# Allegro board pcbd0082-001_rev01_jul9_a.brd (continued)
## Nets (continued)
DDR0_32A_A5: R211.1(N1) U1.T9(DDR0_32A_A5) U17.P2(A5) U18.P2(A5) U19.P2(A5) V1_A-A05.1(PIN) V2_A-A05.1(PIN) V3_A-A05.1(PIN)
DDR0_32A_A6: R212.1(N1) U1.AD7(DDR0_32A_A6) U17.R8(A6) U18.R8(A6) U19.R8(A6) V1_A-A06.1(PIN) V2_A-A06.1(PIN) V3_A-A06.1(PIN)
DDR0_32A_A7: R213.1(N1) U1.R9(DDR0_32A_A7) U17.R2(A7) U18.R2(A7) U19.R2(A7) V1_A-A07.1(PIN) V2_A-A07.1(PIN) V3_A-A07.1(PIN)
DDR0_32A_A8: R214.1(N1) U1.AE7(DDR0_32A_A8) U17.T8(A8) U18.T8(A8) U19.T8(A8) V1_A-A08.1(PIN) V2_A-A08.1(PIN) V3_A-A08.1(PIN)
DDR0_32A_A9: R215.1(N1) U1.AE6(DDR0_32A_A9) U17.R3(A9) U18.R3(A9) U19.R3(A9) V1_A-A09.1(PIN) V2_A-A09.1(PIN) V3_A-A09.1(PIN)
DDR0_32A_A10: R216.1(N1) U1.Y7(DDR0_32A_A10) U17.L7(A10/AP) U18.L7(A10/AP) U19.L7(A10/AP) V1_A-A10.1(PIN) V2_A-A10.1(PIN) V3_A-A10.1(PIN)
DDR0_32A_A11: R217.1(N1) U1.R8(DDR0_32A_A11) U17.R7(A11) U18.R7(A11) U19.R7(A11) V1_A-A11.1(PIN) V2_A-A11.1(PIN) V3_A-A11.1(PIN)
DDR0_32A_A12: R218.1(N1) U1.Y8(DDR0_32A_A12) U17.N7(A12/BC_L) U18.N7(A12/BC_L) U19.N7(A12/BC_L) V1_A-A12.1(PIN) V2_A-A12.1(PIN) V3_A-A12.1(PIN)
DDR0_32A_A13: R219.1(N1) U1.AE8(DDR0_32A_A13) U17.T3(A13) U18.T3(A13) U19.T3(A13) V1_A-A13.1(PIN) V2_A-A13.1(PIN) V3_A-A13.1(PIN)
DDR0_32A_A14: R220.1(N1) U1.R7(DDR0_32A_A14) U17.T7(A14) U18.T7(A14) U19.T7(A14) V1_A-A14.1(PIN) V2_A-A14.1(PIN) V3_A-A14.1(PIN)
DDR0_32A_BA0: R224.1(N1) U1.U9(DDR0_32A_BA0) U17.M2(BA0) U18.M2(BA0) U19.M2(BA0) V1_A-BA0.1(PIN) V2_A-BA0.1(PIN) V3_A-BA0.1(PIN)
DDR0_32A_BA1: R223.1(N1) U1.AB6(DDR0_32A_BA1) U17.N8(BA1) U18.N8(BA1) U19.N8(BA1) V1_A-BA1.1(PIN) V2_A-BA1.1(PIN) V3_A-BA1.1(PIN)
DDR0_32A_BA2: R222.1(N1) U1.AD6(DDR0_32A_BA2) U17.M3(BA2) U18.M3(BA2) U19.M3(BA2) V1_A-BA2.1(PIN) V2_A-BA2.1(PIN) V3_A-BA2.1(PIN)
DDR0_32A_CAS_L: R226.1(N1) U1.AB9(DDR0_32A_CAS_L) U17.K3(CAS_L) U18.K3(CAS_L) U19.K3(CAS_L) V1_A-CAS.1(PIN) V2_A-CAS.1(PIN) V3_A-CAS.1(PIN)
DDR0_32A_CB0: U1.U2(DDR0_32A_CB0) U19.F2(DQ2) V_A-CB0.1(PIN)
DDR0_32A_CB1: U1.T4(DDR0_32A_CB1) U19.H7(DQ7) V_A-CB1.1(PIN)
DDR0_32A_CB2: U1.U4(DDR0_32A_CB2) U19.E3(DQ0) V_A-CB2.1(PIN)
DDR0_32A_CB3: U1.T5(DDR0_32A_CB3) U19.H8(DQ5) V_A-CB3.1(PIN)
DDR0_32A_CB4: U1.T6(DDR0_32A_CB4) U19.F8(DQ3) V_A-CB4.1(PIN)
DDR0_32A_CB5: U1.R5(DDR0_32A_CB5) U19.F7(DQ1) V_A-CB5.1(PIN)
DDR0_32A_CB6: U1.U1(DDR0_32A_CB6) U19.G2(DQ6) V_A-CB6.1(PIN)
DDR0_32A_CB7: U1.T3(DDR0_32A_CB7) U19.H3(DQ4) V_A-CB7.1(PIN)
DDR0_32A_CK0_N: C71.2(N2) R8.1(N1) U1.V7(DDR0_32A_CK_L0) U17.K7(CK_L) U18.K7(CK_L) U19.K7(CK_L)
DDR0_32A_CK0_P: C71.1(N1) R7.1(N1) U1.V8(DDR0_32A_CK_H0) U17.J7(CK) U18.J7(CK) U19.J7(CK)
DDR0_32A_CKE0: R231.1(N1) U1.AC7(DDR0_32A_CKE0) U17.K9(CKE0) U18.K9(CKE0) U19.K9(CKE0)
DDR0_32A_CS0_L: R229.1(N1) U1.W9(DDR0_32A_CS_L0) U17.L2(CS0_L) U18.L2(CS0_L) U19.L2(CS0_L)
DDR0_32A_DM0: U1.AH1(DDR0_32A_DM0) U17.E7(LDM) V_A-DM0.1(PIN)
DDR0_32A_DM1: U1.AD3(DDR0_32A_DM1) U17.D3(UDM) V_A-DM1.1(PIN)
DDR0_32A_DM2: U1.Y5(DDR0_32A_DM2) U18.E7(LDM) V_A-DM2.1(PIN)
DDR0_32A_DM3: U1.V5(DDR0_32A_DM3) U18.D3(UDM) V_A-DM3.1(PIN)
DDR0_32A_DM4: U1.R6(DDR0_32A_DM4) U19.E7(LDM) V_A-DM4.1(PIN)
DDR0_32A_DQ0: U1.AE5(DDR0_32A_DQ0) U17.F2(DQ2) V_A-DQ00.1(PIN)
DDR0_32A_DQ1: U1.AE3(DDR0_32A_DQ1) U17.G2(DQ6) V_A-DQ01.1(PIN)
DDR0_32A_DQ2: U1.AE2(DDR0_32A_DQ2) U17.H8(DQ5) V_A-DQ02.1(PIN)
DDR0_32A_DQ3: U1.AD1(DDR0_32A_DQ3) U17.H7(DQ7) V_A-DQ03.1(PIN)
DDR0_32A_DQ4: U1.AF2(DDR0_32A_DQ4) U17.H3(DQ4) V_A-DQ04.1(PIN)
DDR0_32A_DQ5: U1.AE4(DDR0_32A_DQ5) U17.E3(DQ0) V_A-DQ05.1(PIN)
DDR0_32A_DQ6: U1.AG2(DDR0_32A_DQ6) U17.F7(DQ1) V_A-DQ06.1(PIN)
DDR0_32A_DQ7: U1.AG1(DDR0_32A_DQ7) U17.F8(DQ3) V_A-DQ07.1(PIN)
DDR0_32A_DQ8: U1.AB3(DDR0_32A_DQ8) U17.D7(DQ8) V_A-DQ08.1(PIN)
DDR0_32A_DQ9: U1.AD2(DDR0_32A_DQ9) U17.C3(DQ9) V_A-DQ09.1(PIN)
DDR0_32A_DQ10: U1.AB4(DDR0_32A_DQ10) U17.C8(DQ10) V_A-DQ10.1(PIN)
DDR0_32A_DQ11: U1.AC1(DDR0_32A_DQ11) U17.B8(DQ14) V_A-DQ11.1(PIN)
DDR0_32A_DQ12: U1.AC5(DDR0_32A_DQ12) U17.A2(DQ13) V_A-DQ12.1(PIN)
DDR0_32A_DQ13: U1.AC2(DDR0_32A_DQ13) U17.A7(DQ12) V_A-DQ13.1(PIN)
DDR0_32A_DQ14: U1.AD4(DDR0_32A_DQ14) U17.A3(DQ15) V_A-DQ14.1(PIN)
DDR0_32A_DQ15: U1.AD5(DDR0_32A_DQ15) U17.C2(DQ11) V_A-DQ15.1(PIN)
DDR0_32A_DQ16: U1.AA3(DDR0_32A_DQ16) U18.E3(DQ0) V_A-DQ16.1(PIN)
DDR0_32A_DQ17: U1.AB1(DDR0_32A_DQ17) U18.G2(DQ6) V_A-DQ17.1(PIN)
DDR0_32A_DQ18: U1.AA6(DDR0_32A_DQ18) U18.F7(DQ1) V_A-DQ18.1(PIN)
DDR0_32A_DQ19: U1.AA1(DDR0_32A_DQ19) U18.H3(DQ4) V_A-DQ19.1(PIN)
DDR0_32A_DQ20: U1.Y6(DDR0_32A_DQ20) U18.F8(DQ3) V_A-DQ20.1(PIN)
DDR0_32A_DQ21: U1.AA4(DDR0_32A_DQ21) U18.F2(DQ2) V_A-DQ21.1(PIN)
DDR0_32A_DQ22: U1.Y2(DDR0_32A_DQ22) U18.H8(DQ5) V_A-DQ22.1(PIN)
DDR0_32A_DQ23: U1.Y1(DDR0_32A_DQ23) U18.H7(DQ7) V_A-DQ23.1(PIN)
DDR0_32A_DQ24: U1.W5(DDR0_32A_DQ24) U18.A2(DQ13) V_A-DQ24.1(PIN)
DDR0_32A_DQ25: U1.U5(DDR0_32A_DQ25) U18.C8(DQ10) V_A-DQ25.1(PIN)
DDR0_32A_DQ26: U1.V2(DDR0_32A_DQ26) U18.A7(DQ12) V_A-DQ26.1(PIN)
DDR0_32A_DQ27: U1.V1(DDR0_32A_DQ27) U18.D7(DQ8) V_A-DQ27.1(PIN)
DDR0_32A_DQ28: U1.V4(DDR0_32A_DQ28) U18.B8(DQ14) V_A-DQ28.1(PIN)
DDR0_32A_DQ29: U1.W3(DDR0_32A_DQ29) U18.A3(DQ15) V_A-DQ29.1(PIN)
DDR0_32A_DQ30: U1.W4(DDR0_32A_DQ30) U18.C3(DQ9) V_A-DQ30.1(PIN)
DDR0_32A_DQ31: U1.W6(DDR0_32A_DQ31) U18.C2(DQ11) V_A-DQ31.1(PIN)
DDR0_32A_DQS0_N: U1.AE1(DDR0_32A_DQS_L0) U17.G3(LDQS_L) V_A-DQS0-N.1(PIN)
DDR0_32A_DQS0_P: U1.AF1(DDR0_32A_DQS_H0) U17.F3(LDQS) V_A-DQS0-P.1(PIN)
DDR0_32A_DQS1_N: U1.AC4(DDR0_32A_DQS_L1) U17.B7(UDQS_L) V_A-DQS1-N.1(PIN)
DDR0_32A_DQS1_P: U1.AC3(DDR0_32A_DQS_H1) U17.C7(UDQS) V_A-DQS1-P.1(PIN)
DDR0_32A_DQS2_N: U1.Y4(DDR0_32A_DQS_L2) U18.G3(LDQS_L) V_A-DQS2-N.1(PIN)
DDR0_32A_DQS2_P: U1.Y3(DDR0_32A_DQS_H2) U18.F3(LDQS) V_A-DQS2-P.1(PIN)
DDR0_32A_DQS3_N: U1.W2(DDR0_32A_DQS_L3) U18.B7(UDQS_L) V_A-DQS3-N.1(PIN)
DDR0_32A_DQS3_P: U1.W1(DDR0_32A_DQS_H3) U18.C7(UDQS) V_A-DQS3-P.1(PIN)
DDR0_32A_DQS4_N: U1.T1(DDR0_32A_DQS_L4) U19.G3(LDQS_L) V_A-DQS4-N.1(PIN)
DDR0_32A_DQS4_P: U1.T2(DDR0_32A_DQS_H4) U19.F3(LDQS) V_A-DQS4-P.1(PIN)
DDR0_32A_DRAMRST_L: R272.2(N2) U17.T2(RESET_L) U18.T2(RESET_L) U19.T2(RESET_L)
DDR0_32A_ODT0: R354.1(N1) U1.AA7(DDR0_32A_ODT0) U17.K1(ODT0) U18.K1(ODT0) U19.K1(ODT0)
DDR0_32A_RAS_L: R225.1(N1) U1.AB7(DDR0_32A_RAS_L) U17.J3(RAS_L) U18.J3(RAS_L) U19.J3(RAS_L) V1_A-RAS.1(PIN) V2_A-RAS.1(PIN) V3_A-RAS.1(PIN)
DDR0_32A_VREF: C196.1(N1) R283.2(N2) R284.1(N1) U1.V10(DDR0_VREF) U1.W10(DDR0_VREF_1)
DDR0_32A_VREF0B: C206.1(N1) R288.1(N1) R289.2(N2) U17.H1(VREF_DQ) U17.M8(VREF_CA)
DDR0_32A_VREF1B: C263.1(N1) C264.1(N1) R361.2(N2) R362.1(N1) R363.2(N2) R364.1(N1) U18.H1(VREF_DQ) U18.M8(VREF_CA) U19.H1(VREF_DQ) U19.M8(VREF_CA)
DDR0_32A_WE_L: R227.1(N1) U1.AC6(DDR0_32A_WE_L) U17.L3(WE_L) U18.L3(WE_L) U19.L3(WE_L) V1_A-WE.1(PIN) V2_A-WE.1(PIN) V3_A-WE.1(PIN)
DDR_1.8V: C21.1(N1) L7.1(N1) L12.2(N2) TP44.1 U9.11(OUT4)
DDR_VDDQ: C1.1(N1) C2.1(N1) C66.1(N1) C67.1(N1) C68.1(N1) C76.1(N1) C105.2(N2) C108.1(N1) C111.1(N1) C190.1(N1) C191.1(N1) C192.1(N1) C193.1(N1) C194.1(N1) C195.1(N1) C211.1(N1) C212.1(N1) C213.1(N1) C214.1(N1) C215.1(N1) C216.1(N1) C217.1(N1) C218.1(N1) C219.1(N1) C220.1(N1) C265.1(N1) C266.1(N1) L9.2(N2) R146.2(N2) R284.2(N2) R288.2(N2) R310.2(N2) R335.2(N2) R338.2(N2) R340.2(N2) R362.2(N2) R364.2(N2) TP54.1 U1.AA2(VDDQ_DDR0) U1.AA5(VDDQ_DDR0_1) U1.AA8(VDDQ_DDR0_2) U1.AE9(VDDQ_DDR0_3) U1.AH2(VDDQ_DDR0_4) U1.B2(VDDQ_DDR0_5) U1.B4(VDDQ_DDR0_6) U1.B6(VDDQ_DDR0_7) U1.B8(VDDQ_DDR0_8) U1.C9(VDDQ_DDR0_9) U1.E4(VDDQ_DDR0_10) U1.E8(VDDQ_DDR0_11) U1.H10(VDDQ_DDR0_12) U1.J3(VDDQ_DDR0_13) U1.J6(VDDQ_DDR0_14) U1.N2(VDDQ_DDR0_15) U1.N5(VDDQ_DDR0_16) U1.N8(VDDQ_DDR0_17) U1.T10(VDDQ_DDR0_18) U1.U3(VDDQ_DDR0_19) U1.U6(VDDQ_DDR0_20) U3.2(VLDOIN) U17.A1(VDDQ8) U17.A8(VDDQ3) U17.B2(VDD6) U17.C1(VDDQ7) U17.C9(VDDQ2) U17.D2(VDDQ5) U17.D9(VDD2) U17.E9(VDDQ1) U17.F1(VDDQ6) U17.G7(VDD4) U17.H2(VDDQ4) U17.H9(VDDQ0) U17.K2(VDD5) U17.K8(VDD3) U17.N1(VDD8) U17.N9(VDD1) U17.R1(VDD7) U17.R9(VDD0) U18.A1(VDDQ8) U18.A8(VDDQ3) U18.B2(VDD6) U18.C1(VDDQ7) U18.C9(VDDQ2) U18.D2(VDDQ5) U18.D9(VDD2) U18.E9(VDDQ1) U18.F1(VDDQ6) U18.G7(VDD4) U18.H2(VDDQ4) U18.H9(VDDQ0) U18.K2(VDD5) U18.K8(VDD3) U18.N1(VDD8) U18.N9(VDD1) U18.R1(VDD7) U18.R9(VDD0) U19.A1(VDDQ8) U19.A8(VDDQ3) U19.B2(VDD6) U19.C1(VDDQ7) U19.C9(VDDQ2) U19.D2(VDDQ5) U19.D9(VDD2) U19.E9(VDDQ1) U19.F1(VDDQ6) U19.G7(VDD4) U19.H2(VDDQ4) U19.H9(VDDQ0) U19.K2(VDD5) U19.K8(VDD3) U19.N1(VDD8) U19.N9(VDD1) U19.R1(VDD7) U19.R9(VDD0)
DDR_VTT: C108.2(N2) C109.1(N1) C110.1(N1) C111.2(N2) C136.1(N1) C137.1(N1) C138.1(N1) C139.1(N1) C140.1(N1) R206.2(N2) R207.2(N2) R208.2(N2) R209.2(N2) R210.2(N2) R211.2(N2) R212.2(N2) R213.2(N2) R214.2(N2) R215.2(N2) R216.2(N2) R217.2(N2) R218.2(N2) R219.2(N2) R220.2(N2) R222.2(N2) R223.2(N2) R224.2(N2) R225.2(N2) R226.2(N2) R227.2(N2) R229.2(N2) R231.2(N2) R337.2(N2) R354.2(N2) TP52.1 U3.3(VTT)
DEBUG_CPLD_PGRM_JTAG_TCK: J5.15 R65.1(N1) TP10.1 U12.2(1B1)
DEBUG_CPLD_PGRM_JTAG_TDI: J5.17 R71.2(N2) TP13.1 U12.5(2B1)
DEBUG_CPLD_PGRM_JTAG_TDO: J5.19 R70.2(N2) TP12.1 U12.11(3B1)
DEBUG_CPLD_PGRM_JTAG_TMS: J5.21 R69.2(N2) TP11.1 U12.14(4B1)
EXT_3.3V: C24.1(N1) C36.1(N1) C83.1(N1) C84.1(N1) C118.1(N1) C119.1(N1) C120.1(N1) C121.1(N1) C122.1(N1) C123.1(N1) C284.1(N1) C285.1(N1) DS1.1(A) J4.146(ROW19) J4.154(ROW20) J5.3 J5.28 R14.1(N1) R15.1(N1) R48.1(N1) R50.1(N1) R52.1(N1) R53.1(N1) R61.1(N1) R62.1(N1) R63.1(N1) R69.1(N1) R70.1(N1) R71.1(N1) R73.1(N1) R85.2(N2) R86.2(N2) R87.2(N2) R99.2(N2) R100.2(N2) R106.2(N2) R130.2(N2) R131.2(N2) R267.2(N2) R278.2(N2) R369.2(N2) R370.2(N2) R373.2(N2) R374.2(N2) R377.2(N2) R378.2(N2) R379.2(N2) R380.2(N2) R395.1(N1) R396.1(N1) R397.1(N1) R398.1(N1) R399.1(N1) U2.A1(VCC_1) U2.B10(VCCIO0_0) U2.C5(VCCIO0_1) U2.D3(VCCIO3_0) U2.D14(VCCIO1_1) U2.L1(VCCIO3_1) U2.L12(VCCIO1_0) U2.N11(VCCIO2_1) U2.P1(VCCIO2_0) U2.P14(VCC_0) U4.8(V+) U12.16(VCC) U14.9(VDD2) U14.19(VDD1) U20.16(VCC) U21.16(VCC)
EXT_3.3V_PGOOD: R102.2(N2) R121.2(N2) TP63.1 U2.C3(PL2B) U4.7(OUT2)
EXT_3.3V_THRESHOLD: C249.1(N1) R121.1(N1) R267.1(N1) R316.2(N2) U4.5(IN2+)
EXT_12.0V: C126.1(N1) C130.1(N1) C179.1(N1) C180.1(N1) C183.1(N1) C184.1(N1) C242.1(POS) C243.1(POS) J4.145(ROW19) J4.153(ROW20) Q1.1(VIN1) Q1.2(VIN2) R279.2(N2) R312.1(N1) R401.1(N1) R402.1(N1) U5.8(VIN1) U5.9(VIN2) U5.10(VIN3) U5.11(VIN4) U5.12(VIN5) U5.13(VIN6) U5.14(VIN7) U5.42(VIN8) U6.8(VIN1) U6.9(VIN2) U6.10(VIN3) U6.11(VIN4) U6.12(VIN5) U6.13(VIN6) U6.14(VIN7) U6.42(VIN8) U13.2(VCC_1) U13.3(VCC_2) U13.11(VCC_3)
EXT_12.0V_PGOOD: R101.2(N2) R122.2(N2) TP62.1 U2.C1(PL2A) U4.1(OUT1)
EXT_12.0V_THRESHOLD: C248.1(N1) R122.1(N1) R279.1(N1) R317.2(N2) U4.3(IN1+)
GH_PHASE1: TP32.1 U6.6(GH)
GH_PHASE2: TP33.1 U5.6(GH)
GL_PHASE1: TP36.1 U6.36(GL)
GL_PHASE2: TP31.1 U5.36(GL)
HOST_RESET_REQ_L: J5.16 R48.2(N2) TP18.1 U2.H1(PL5C)
L_1_CORE_PHASE: L17.1(N1) R116.2(N2) R171.1(N1) U6.15(VSWH1) U6.29(VSWH2) U6.30(VSWH3) U6.31(VSWH4) U6.32(VSWH5) U6.33(VSWH6) U6.34(VSWH7) U6.35(VSWH8) U6.43(VSWH9)
L_2_CORE_PHASE: L18.1(N1) R117.2(N2) R168.1(N1) U5.15(VSWH1) U5.29(VSWH2) U5.30(VSWH3) U5.31(VSWH4) U5.32(VSWH5) U5.33(VSWH6) U5.34(VSWH7) U5.35(VSWH8) U5.43(VSWH9)
MAIN_3.3V: J4.147(ROW19) J4.155(ROW20) J4.156(ROW20) TP68.1
MH_1: R152.1(N1)
MH_2: R149.2(N2)
MUX_NFP_GPIO0_NWK0_I2C_SCL: R385.2(N2) U1.Y28(GPIO0) U21.3(1B2)
MUX_NFP_GPIO1_NWK0_I2C_SDA: R386.2(N2) U1.W28(GPIO1) U21.6(2B2)
MUX_NFP_GPIO2_NWK1_I2C_SCL: R387.2(N2) U1.Y29(GPIO2) U21.10(3B2)
MUX_NFP_GPIO3_NWK1_I2C_SDA: R388.2(N2) U1.W29(GPIO3) U21.13(4B2)
MUX_NFP_PCIE0_WAKE_L: R384.2(N2) U1.AE28(GPIO15) U20.13(4B2)
MUX_NFP_SMBUS_ALERT_L: R381.2(N2) U1.AD30(GPIO18) U20.3(1B2)
MUX_NFP_SMBUS_SCL: R383.2(N2) U1.AD29(GPIO16) U20.10(3B2)
MUX_NFP_SMBUS_SDA: R382.2(N2) U1.AE29(GPIO17) U20.6(2B2)
NFP_ARM_SPI_FLASH_MISO: R20.2(N2) U1.P29(SPI0_MISO) U7.2(DQ1/MISO) U15.2(DQ1/MISO)
NFP_ARM_SPI_FLASH_MOSI: R23.2(N2) R201.2(N2) U7.5(DQ0/MOSI) U15.5(DQ0/MOSI)
NFP_ARM_SPI_FLASH_SCK: R22.2(N2) R204.2(N2) U7.6(C) U15.6(C)
NFP_ARM_SPI_FLASH_SEL: R28.2(N2) R32.1(N1) R282.2(N2) U7.1(CS_L) U15.1(CS_L)
NFP_ARM_SPI_FLASH_WP_L: R29.2(N2) U1.AA29(GPIO5) U7.3(WP_L/DQ2) U15.3(WP_L/DQ2)
NFP_CFG_SPI_FLASH_HOLD_L: J5.23 R25.2(N2) TP24.1 U2.K12(PR6B) U8.7(DQ3/HOLD_L)
NFP_CFG_SPI_FLASH_MISO: R24.2(N2) U1.V30(SPI1_CFG_MISO) U8.2(DQ1/MISO)
NFP_CFG_SPI_FLASH_MOSI: R27.2(N2) R202.2(N2) U8.5(DQ0/MOSI)
NFP_CFG_SPI_FLASH_SCK: R26.2(N2) R205.2(N2) U8.6(C)
NFP_CFG_SPI_FLASH_SEL: R18.1(N1) R30.2(N2) R281.2(N2) U8.1(CS_L)
NFP_CFG_SPI_FLASH_WP_L: R31.2(N2) U2.K14(PR6D) U8.3(WP_L/DQ2)
NFP_CLK_NRESET_L: R410.2(N2) U1.M28(CLK_NRESET_L)
NFP_CLK_NRESET_OUT_L: R19.2(N2) U1.M31(CLK_NRESET_OUT_L) U2.J1(PL6A)
NFP_CLK_REF_N: R135.2(N2) R321.2(N2) U1.T27(CLK_REF_L)
NFP_CLK_REF_P: R134.2(N2) R320.2(N2) U1.R27(CLK_REF_H)
NFP_CORE_PWM1: U6.40(PWM) U10.29(PWM1)
NFP_CORE_PWM2: U5.40(PWM) U10.28(PWM2)
NFP_CORE_VID0: R179.1(N1) U1.AJ31(VID0)
NFP_CORE_VID1: R176.1(N1) U1.AG31(VID1)
NFP_CORE_VID2: R172.1(N1) U1.AH32(VID2)
NFP_CORE_VID3: R175.1(N1) U1.AJ32(VID3)
NFP_CORE_VID4: R174.1(N1) U1.AG32(VID4)
NFP_CORE_VID5: R177.1(N1) U1.AH31(VID5)
NFP_CORE_VID6: R173.1(N1) U1.AF32(VID6)
NFP_CORE_VID7: R178.1(N1) U1.AG30(VID7)
NFP_CPLD_INT_L: R58.1(N1) U1.AA28(GPIO4) U2.L14(PR7A)
NFP_CPLD_PRGM_JTAG_TCK: R64.1(N1) U1.AD28(GPIO14) U12.3(1B2)
NFP_CPLD_PRGM_JTAG_TDI: R68.2(N2) U1.AC27(GPIO13) U12.6(2B2)
NFP_CPLD_PRGM_JTAG_TDO: R67.2(N2) U1.AC28(GPIO12) U12.10(3B2)
NFP_CPLD_PRGM_JTAG_TMS: R66.2(N2) U1.AC30(GPIO11) U12.13(4B2)
NFP_FAIL_SAFE_BOOT_L: J5.14 R16.1(N1) R34.1(N1) TP17.1 U1.AB30(GPIO7) U2.M10(PB14A)
NFP_JTAG_ARM_TCK: J5.5 R408.1(N1) TP6.1 U1.AA31(JTAG_ARM_TCK)
NFP_JTAG_ARM_TDI: J5.7 R147.1(N1) R403.2(N2) TP7.1 U1.Y32(JTAG_ARM_TDI)
NFP_JTAG_ARM_TDO: J5.9 R147.2(N2) R263.2(N2) R404.2(N2) TP8.1
NFP_JTAG_ARM_TMS: J5.11 R405.2(N2) TP9.1 U1.AA32(JTAG_ARM_TMS)
NFP_JTAG_ARM_TRST_L: J5.13 R406.2(N2) R407.1(N1) TP5.1 U1.Y31(JTAG_ARM_TRST)
NFP_PCIE0_PER0_N: C154.2(N2) J4.83(ROW11)
NFP_PCIE0_PER0_P: C153.2(N2) J4.75(ROW10)
NFP_PCIE0_PER1_N: C156.2(N2) J4.100(ROW13)
NFP_PCIE0_PER1_P: C155.2(N2) J4.92(ROW12)
NFP_PCIE0_PER2_N: C158.2(N2) J4.115(ROW15)
NFP_PCIE0_PER2_P: C157.2(N2) J4.107(ROW14)
NFP_PCIE0_PER3_N: C160.2(N2) J4.132(ROW17)
NFP_PCIE0_PER3_P: C159.2(N2) J4.124(ROW16)
NFP_PCIE0_PER4_N: C146.2(N2) J4.68(ROW9)
NFP_PCIE0_PER4_P: C145.2(N2) J4.60(ROW8)
NFP_PCIE0_PER5_N: C148.2(N2) J4.51(ROW7)
NFP_PCIE0_PER5_P: C147.2(N2) J4.43(ROW6)
NFP_PCIE0_PER6_N: C150.2(N2) J4.36(ROW5)
NFP_PCIE0_PER6_P: C149.2(N2) J4.28(ROW4)
NFP_PCIE0_PER7_N: C152.2(N2) J4.19(ROW3)
NFP_PCIE0_PER7_P: C151.2(N2) J4.11(ROW2)
NFP_PCIE0_PET0_N: J4.17(ROW3) U1.AG12(PCIE0_RXN0)
NFP_PCIE0_PET0_P: J4.9(ROW2) U1.AH12(PCIE0_RXP0)
NFP_PCIE0_PET1_N: J4.34(ROW5) U1.AH13(PCIE0_RXN1)
NFP_PCIE0_PET1_P: J4.26(ROW4) U1.AJ13(PCIE0_RXP1)
NFP_PCIE0_PET2_N: J4.49(ROW7) U1.AG14(PCIE0_RXN2)
NFP_PCIE0_PET2_P: J4.41(ROW6) U1.AH14(PCIE0_RXP2)
NFP_PCIE0_PET3_N: J4.66(ROW9) U1.AH15(PCIE0_RXN3)
NFP_PCIE0_PET3_P: J4.58(ROW8) U1.AJ15(PCIE0_RXP3)
NFP_PCIE0_PET4_N: J4.81(ROW11) U1.AG16(PCIE0_RXN4)
NFP_PCIE0_PET4_P: J4.73(ROW10) U1.AH16(PCIE0_RXP4)
NFP_PCIE0_PET5_N: J4.98(ROW13) U1.AH17(PCIE0_RXN5)
NFP_PCIE0_PET5_P: J4.90(ROW12) U1.AJ17(PCIE0_RXP5)
NFP_PCIE0_PET6_N: J4.113(ROW15) U1.AG18(PCIE0_RXN6)
NFP_PCIE0_PET6_P: J4.105(ROW14) U1.AH18(PCIE0_RXP6)
NFP_PCIE0_PET7_N: J4.130(ROW17) U1.AH19(PCIE0_RXN7)
NFP_PCIE0_PET7_P: J4.122(ROW16) U1.AJ19(PCIE0_RXP7)
NFP_PCIE0_RESET_OUT_L: R409.2(N2) U2.P6(PB6D/PCLKC2_0)
NFP_PCIE0_WAKE_L: R368.1(N1) R380.1(N1) R384.1(N1) U20.12(4A)
NFP_PGOOD4: R56.1(N1) U1.R28(PWRGOOD4) U2.N14(PR7D)
NFP_REF_CLK_100M_EN: R268.1(N1) U2.K3(PL7B/PCLKC3_0)
NFP_REF_CLK_156M_EN: R269.1(N1) U2.M1(PL7C)
NFP_SERDES0_RX0_N: J4.149(ROW19) U1.AG20(SERDES0_RXN0)
NFP_SERDES0_RX0_P: J4.141(ROW18) U1.AH20(SERDES0_RXP0)
NFP_SERDES0_TX0_N: J4.134(ROW17) U1.AK20(SERDES0_TXN0)
NFP_SERDES0_TX0_P: J4.126(ROW16) U1.AL20(SERDES0_TXP0)
NFP_SERDES1_RX0_N: J4.104(ROW13) U1.AG24(SERDES1_RXN0)
NFP_SERDES1_RX0_P: J4.96(ROW12) U1.AH24(SERDES1_RXP0)
NFP_SERDES1_RX1_N: J4.111(ROW14) U1.AH25(SERDES1_RXN1)
NFP_SERDES1_RX1_P: J4.119(ROW15) U1.AJ25(SERDES1_RXP1)
NFP_SERDES1_RX2_N: J4.128(ROW16) U1.AG26(SERDES1_RXN2)
NFP_SERDES1_RX2_P: J4.136(ROW17) U1.AH26(SERDES1_RXP2)
NFP_SERDES1_RX3_N: J4.143(ROW18) U1.AH27(SERDES1_RXN3)
NFP_SERDES1_RX3_P: J4.151(ROW19) U1.AJ27(SERDES1_RXP3)
NFP_SERDES1_TX0_N: J4.40(ROW5) U1.AK24(SERDES1_TXN0)
NFP_SERDES1_TX0_P: J4.32(ROW4) U1.AL24(SERDES1_TXP0)
NFP_SERDES1_TX1_N: J4.55(ROW7) U1.AL25(SERDES1_TXN1)
NFP_SERDES1_TX1_P: J4.47(ROW6) U1.AM25(SERDES1_TXP1)
NFP_SERDES1_TX2_N: J4.72(ROW9) U1.AK26(SERDES1_TXN2)
NFP_SERDES1_TX2_P: J4.64(ROW8) U1.AL26(SERDES1_TXP2)
NFP_SERDES1_TX3_N: J4.87(ROW11) U1.AL27(SERDES1_TXN3)
NFP_SERDES1_TX3_P: J4.79(ROW10) U1.AM27(SERDES1_TXP3)
NFP_SERDES012_SYSCLK_IN_N: R132.2(N2) R322.2(N2) U1.AE26(SERDES012_SYSCLK_INN)
NFP_SERDES012_SYSCLK_IN_P: R133.2(N2) R319.2(N2) U1.AE25(SERDES012_SYSCLK_INP)
NFP_SMBUS_ALERT_L: R379.1(N1) R381.1(N1) R391.1(N1) U20.4(1A)
NFP_SMBUS_SCL: R370.1(N1) R383.1(N1) R389.1(N1) U20.9(3A)
NFP_SMBUS_SDA: R351.1(N1) R369.1(N1) R382.1(N1) U20.7(2A)
NFP_SPI2_CS: U1.W31(SPIX_SEL2) U2.P11(PB14B)
NFP_SPI2_MISO: U1.V31(SPIX_D2) U2.N4(PB6B/SO/SPISO)
NFP_SPI2_MOSI: R203.2(N2) U2.P13(PB14D/SISPI)
NFP_SPI2_SCK: R199.2(N2) U2.M4(PB6A/MCLK/CCLK)
NFP_SRESET_L: R57.1(N1) U1.M29(SRESET_L) U2.N13(PR7C)
NFP_UART_SR_RX: J5.25 TP25.1 U1.N31(SR_RX)
NFP_UART_SR_TX: J5.26 R200.2(N2) TP19.1
NFP_VDD_CORE_IMON: C125.2(N2) R323.1(N1) TP38.1 U10.8(IMON)
NFP_VDD_CORE_ISEN1_N: R110.2(N2) R166.2(N2)
NFP_VDD_CORE_ISEN1_P: R171.2(N2) R314.2(N2) R325.2(N2)
NFP_VDD_CORE_ISEN2_N: R111.2(N2) R167.2(N2)
NFP_VDD_CORE_ISEN2_P: R168.2(N2) R315.2(N2) R324.2(N2)
NFP_VDD_CORE_SENSE_VDD: R182.2(N2) R286.1(N1) R313.2(N2) U1.AC25(VDD_CORE1_SENSE)
NFP_VDD_CORE_SENSE_VSS: C82.1(N1) C125.1(N1) R285.2(N2) R323.2(N2) U1.AC24(VSS_SENSE1) U10.13(FBRTN)
NFP_VDD_CORE_TCOMPA: C34.2(N2) C35.2(N2) R2.2(N2) R327.2(N2) R329.1(N1) U10.18(CSCOMP)
NFP_VDD_CORE_TCOMPB: R2.1(N1) R13.1(N1) R329.2(N2)
NWK0_I2C_SCL: J4.160(ROW20) R377.1(N1) R385.1(N1) U21.4(1A)
NWK0_I2C_SDA: J4.152(ROW19) R373.1(N1) R386.1(N1) U21.7(2A)
NWK0_LED_ACT_G_L: J4.94(ROW12) U2.C4(PT6D)
NWK0_LED_LINK_G_L: J4.102(ROW13) U2.B3(PT6B)
NWK0_MOD_PRES_L: J4.158(ROW20) U2.B7(PT9B/PCLKC0_1)
NWK1_I2C_SCL: J4.137(ROW18) R374.1(N1) R387.1(N1) U21.9(3A)
NWK1_I2C_SDA: J4.129(ROW17) R378.1(N1) R388.1(N1) U21.12(4A)
NWK1_LED_ACT_G_L: J4.109(ROW14) U2.A13(PT11D/DONE)
NWK1_LED_LINK_G_L: J4.117(ROW15) U2.N3(PB4C)
NWK1_MOD_PRES_L: J4.14(ROW2) U2.C13(PR2B)
PCIE0_REFCLK_N: J4.16(ROW2) U1.AE14(PCIE0_SYSCLK_INN)
PCIE0_REFCLK_P: J4.8(ROW1) U1.AE13(PCIE0_SYSCLK_INP)
PCIE0_RST_L: J4.2(ROW1) R73.2(N2) U1.P30(PCIE0_RESET_IN_L) U2.M2(PL7D)
PCIE0_WAKE_L: J4.4(ROW1) R367.2(N2) R368.2(N2)
PGRM_JTAG_TCK: R45.1(N1) TP27.1 U1.AB32(JTAG_TCK)
PGRM_JTAG_TDI: R44.2(N2) R148.1(N1) TP28.1 U1.AD32(JTAG_TDI)
PGRM_JTAG_TDO: R43.2(N2) R148.2(N2) R262.2(N2) TP29.1
PGRM_JTAG_TMS: R42.2(N2) TP30.1 U1.AC31(JTAG_TMS)
PGRM_JTAG_TRST_L: R41.2(N2) R46.1(N1) TP26.1 U1.AB31(JTAG_TRST)
PSU_I2C_SCL: J5.8 R131.1(N1) R138.2(N2) TP15.1 U2.C8(PT9C/SCL/PCLKT0_0) U9.15(SCL) U10.5(SCL)
PSU_I2C_SDA: J5.10 R130.1(N1) R139.2(N2) TP16.1 U2.B8(PT9D/SDA/PCLKC0_0) U9.13(SDA) U10.4(SDA)
PWR_GOOD_LED_L: J5.6 R277.1(N1) TP14.1 U2.F14(PR3D)
SMBUS_ALERT_L: J4.6(ROW1) R391.2(N2) R392.2(N2)
SMBUS_SCL: J4.13(ROW2) R389.2(N2) R390.2(N2)
SMBUS_SDA: J4.21(ROW3) R350.2(N2) R351.2(N2)
VR_OD1_L: R170.1(N1) U10.21(~OD1)
VR_ODN_L: R169.1(N1) U10.20(~ODN)

Pads without a net: U17 J1 J9 L1 L9 M7; U18 J1 J9 L1 L9 M7; U19 J1 J9 L1 L9 M7

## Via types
v1: diameter 0.762, hole 0.381, TOP to BOTTOM, 112 vias
v2: diameter 0.483, hole 0.206, TOP to BOTTOM, 731 vias
v3: diameter 0.457, hole 0.206, TOP to BOTTOM, 226 vias
v4: diameter 0.508, hole 0.257, TOP to BOTTOM, 297 vias
v5: diameter 0.508, hole 0.254, TOP to BOTTOM, 341 vias
v6: diameter 0.762, hole 0.267, TOP to BOTTOM, 27 vias
v7: diameter 0.508, hole 0.267, TOP to BOTTOM, 54 vias
v8: diameter 0.483, hole 0.257, TOP to BOTTOM, 79 vias
v9: diameter 0.61, hole 0.257, TOP to BOTTOM, 52 vias
v10: diameter 0.762, hole 0.206, TOP to BOTTOM, 3 vias
v11: diameter 1.016, hole 0.508, TOP to BOTTOM, 12 vias
v12: diameter 0.762, hole 0.257, TOP to BOTTOM, 1 via
v13: diameter 0.762, hole 0.254, TOP to BOTTOM, 16 vias

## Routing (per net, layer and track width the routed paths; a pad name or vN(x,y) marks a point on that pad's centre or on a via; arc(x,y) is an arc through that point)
0.7V_REF: length 12.4
  TOP w0.147: U4.2 48.3,10.13 48.63,9.8 48.63,9.17 49.26,8.53 v5(49.64,8.53) 49.64,9.1 50.02,9.48 U4.6 ; v4(49.01,4.09) 49.05,4.13 R278.1
  08_SIG w0.121: v4(49.01,4.09) 49.01,7.9 v5(49.64,8.53)
GND: length 668.2
  TOP w0.127: v3(33.46,38.53) 33.05,38.11 33.05,37.22 33.41,36.85 U2.P10 ; v3(36.74,38.53) 36.4,38.21 36.4,37.54 35.91,37.05 U2.P5
  TOP w0.147: U2.A5 35.91,29.95 v3(35.04,29.08)
  TOP w0.203: R60.2 R65.2 R64.2 R72.2 ; v9(33.01,19.45) 32.49,19.97 U10.7 ; v5(69.96,13.87) 69.71,13.61 R113.1 ; U14.4 36.55,51.09 v9(36.44,51.2) 36.05,50.82 U14.3 ; C182.2 51.04,6.53 49.95,6.53 49.89,6.59 C249.2 R316.1 ; TP43.1 22.59,11.2 21.7,10.31 21.7,10.2 21.14,9.64 20.74,9.64 20.26,10.12 v4(19.67,10.12) ; U3.21 v4(85.28,16.81) 85.6,16.5 U3.10 ; v7(87.36,22.12) R105.1 R107.1 R318.1 ; 20.82,19.71 20.51,20.01 20.43,20.01 20.43,20.01 U9.10 ; 16.5,21.61 U9.32 15.1,21.61 15.03,21.54 15.02,21.54 14.88,21.41 14.88,21.4 14.59,21.11 ; U9.36 14.77,20.01 14.4,19.64 ; R317.1 v4(46.47,6.59) ; U13.14 65.9,9.29 v4(66.15,9.55) ; C81.2 v4(29.83,14.06) ; U9.22 18.04,24.32 v5(18.14,24.59) ; v9(25.13,25.93) 24.88,26.18 U12.8 ; R101.1 45.8,11.62 v5(45.83,11.58) ; 18.39,18.73 18.26,18.86 18.24,18.86 18.04,19.06 U9.6 ; v4(66.15,8.53) 65.9,8.79 U13.15 ; v5(48.37,8.53) 48.08,8.83 U4.4 ; U14.14 35.05,53.86 v9(35.17,53.74) 35.55,54.13 U14.13 ; C82.2 29.37,17.51 R308.1 R1.1 ; U9.14 19.04,21.61 ; R400.1 50.24,14.15 v5(50.36,14.27) ; U9.18 19.87,23.21 20.23,23.57 20.23,23.7 ; U3.4 84.23,16.9 v4(84.32,16.81) 84.4,16.73 U3.7 ; v4(67.17,8.53) 67.41,8.29 U13.4 ; v5(17.74,22.99) 17.64,23.2 U9.23 ; U9.28 15.02,23.21 14.59,23.65 ; R103.1 v7(3.8,25.8) TP47.1
  TOP w0.254: R371.2 21.7,57.08 v5(21.7,56.67) 22.12,56.25 C284.2 ; C215.2 83.55,38.42 83.55,38.76 83.76,38.97 v3(84.21,38.97) ; v2(58.9,54.28) U1.AK15 ; v2(63.9,39.28) U1.T11 ; U1.A26 v2(47.9,24.28) ; v2(60.9,43.28) U1.W14 ; U1.P25 v2(48.9,37.28) ; v2(65.9,24.28) U1.A9 ; v2(63.9,46.28) U1.AB11 ; U1.A20 v2(53.9,24.28) ; U1.H23 v2(50.9,31.28) ; v2(69.9,24.28) U1.A5 ; v2(58.9,24.28) U1.A16 ; U1.L22 v2(51.9,34.28) ; v2(64.9,53.28) U1.AJ10 ; U1.AC26 v2(47.9,47.28) ; U1.R24 v2(49.9,38.28) ; U1.AH22 U1.AH21 U1.AJ21 ; U1.AH22 U1.AG22 ; U1.AH22 U1.AH23 U1.AJ23 v2(50.9,53.28) ; U1.L24 v2(49.9,34.28) ; U1.C26 v2(47.9,26.28) ; U1.R22 v2(51.9,38.28) ; v2(65.9,25.28) U1.B9 ; U1.D28 v2(45.9,27.28) ; U1.V17 v2(56.9,42.28) ; U1.R20 v2(53.9,38.28) ; U1.J18 v2(55.9,32.28) ; v2(66.9,50.28) U1.AF8 ; U1.B21 v2(52.9,25.28) ; v3(81.81,51.33) 81.77,51.37 C213.2 ; v2(60.9,41.28) U1.U14 ; U1.F31 v2(42.9,29.28) ; U1.B19 v2(54.9,25.28) ; v2(59.9,42.28) U1.V15 ; U1.M25 v2(48.9,35.28) ; U1.E22 v2(51.9,28.28) ; v2(63.9,35.28) U1.M11 ; v2(61.9,51.28) U1.AG13 ; U1.U24 v2(49.9,41.28) ; U1.AB17 v2(56.9,46.28) ; U1.AH30 v2(43.9,52.28) ; U1.AH4 U1.AG4 ; U1.AH4 v2(70.9,52.28) ; U1.AH4 U1.AH5 U1.AH6 ; v2(66.9,53.28) U1.AJ8 ; v2(58.9,53.28) U1.AJ16 ; v2(63.9,54.28) U1.AK11 ; v2(63.9,27.28) U1.D11 ; v2(62.9,49.28) U1.AE12 ; U1.J24 v2(49.9,32.28) ; U1.AD25 v2(48.9,48.28) ; U1.M21 v2(52.9,35.28) ; U1.N29 v2(44.9,36.28) ; U1.F27 v2(46.9,29.28) ; v2(68.9,50.28) U1.AF6 ; v2(68.9,56.28) U1.AM6 ; v2(63.9,51.28) U1.AG11 ; v5(76.31,15.14) 76.31,15.77 76.57,16.03 TP53.1 ; v3(81.81,39.77) 81.81,39.22 81.61,39.01 R352.1 ; U1.H17 v2(56.9,31.28) ; U1.AM20 v2(53.9,56.28) ; U1.AM18 v2(55.9,56.28) ; U1.AA20 v2(53.9,45.28) ; U1.AC29 v2(44.9,47.28) ; U1.E24 v2(49.9,28.28) ; U1.AJ20 v2(53.9,53.28) ; v2(62.9,36.28) U1.N12 ; U1.AJ22 v2(52.9,53.28) ; v2(59.9,39.28) U1.T15 ; R353.1 84.09,25.83 84.2,25.94 C218.2 84.21,26.63 v3(84.21,27.41) ; v2(62.9,45.28) U1.AA12 ; U1.R18 v2(55.9,38.28) ; v2(66.9,29.28) U1.F8 ; U1.AD19 v2(54.9,48.28) ; U1.T21 v2(52.9,39.28) ; v2(64.9,49.28) U1.AE10 ; v2(70.9,53.28) U1.AJ4 ; U1.AG27 v2(46.9,51.28) ; C265.2 77.11,46.27 v3(77.01,46.17) ; U1.AK29 v2(44.9,54.28) ; U1.AE11 v2(63.9,49.28) ; U1.AF26 v2(47.9,50.28) ; U1.T25 v2(48.9,39.28) ; U1.AJ26 v2(47.9,53.28) ; v2(63.9,37.28) U1.P11 ; v2(59.9,44.28) U1.Y15 ; v2(64.9,29.28) U1.F10 ; U1.V23 v2(50.9,42.28) ; U1.AA26 v2(47.9,45.28) ; v2(61.9,35.28) U1.M13 ; v2(59.9,25.28) U1.B15 ; v2(62.9,47.28) U1.AC12 ; U1.G22 v2(51.9,30.28) ; U1.AJ28 v2(45.9,53.28) ; v2(72.9,54.28) U1.AK2 ; v2(62.9,28.28) U1.E12 ; v2(64.9,50.28) U1.AF10 ; U1.U22 v2(51.9,41.28) ; v2(62.9,34.28) U1.L12 ; U1.AA22 v2(51.9,45.28) ; v3(78.61,38.97) 78.64,38.94 C266.2 ; v2(59.9,37.28) U1.P15 ; v2(71.9,52.28) U1.AH3 ; U1.V29 v2(44.9,42.28) ; U1.AJ18 v2(55.9,53.28) ; U1.AC20 v2(53.9,47.28) ; U1.AM26 v2(47.9,56.28) ; U1.D19 v2(54.9,27.28) ; U1.AB19 v2(54.9,46.28) ; U1.W27 v2(46.9,43.28) ; U1.M19 v2(54.9,35.28) ; U1.U18 v2(55.9,41.28) ; v2(72.9,37.28) U1.P2 ; v2(64.9,27.28) U1.D10 ; v2(58.9,45.28) U1.AA16 ; U1.U20 v2(53.9,41.28) ; U1.Y25 v2(48.9,44.28) ; U1.P21 v2(52.9,37.28) ; U1.K17 v2(56.9,33.28) ; U1.T19 v2(54.9,39.28) ; U1.AB25 v2(48.9,46.28) ; v2(60.9,45.28) U1.AA14 ; U1.F17 v2(56.9,29.28) ; v2(68.9,42.28) U1.V6 ; v2(66.9,46.28) U1.AB8 ; v2(71.9,50.28) U1.AF3 ; v2(69.9,37.28) U1.P5 ; U1.Y19 v2(54.9,44.28) ; U1.AG19 v2(54.9,51.28) ; v2(60.9,53.28) U1.AJ14 ; v2(58.9,41.28) U1.U16 ; U1.AG21 v2(52.9,51.28) ; v2(67.9,51.28) U1.AG7 ; U1.D25 v2(48.9,27.28) ; v2(58.9,34.28) U1.L16 ; v2(59.9,29.28) U1.F15 ; U1.AJ11 U1.AH11 U1.AH10 ; v2(61.9,25.28) U1.B13 ; U1.AB23 v2(50.9,46.28) ; U1.AK17 v2(56.9,54.28) ; v2(69.9,25.28) U1.B5 ; U1.AD23 v2(50.9,48.28) ; v2(59.9,33.28) U1.K15 ; v2(62.9,43.28) U1.W12 ; U1.J20 v2(53.9,32.28) ; v2(60.9,28.28) U1.E14 ; v2(62.9,38.28) U1.R12 ; U1.N20 v2(53.9,36.28) ; U1.V28 v2(45.9,42.28) ; U1.AF24 v2(49.9,50.28) ; U1.AE27 v2(46.9,49.28) ; v2(61.9,54.28) U1.AK13 ; U1.W30 v2(43.9,43.28) ; U1.V25 v2(48.9,42.28) ; U1.H19 v2(54.9,31.28) ; U1.B23 v2(50.9,25.28) ; U1.AH10 U1.AG10 ; U1.AH10 U1.AH9 U1.AH8 ; v2(65.9,51.28) U1.AG9 ; v2(69.9,54.28) U1.AK5 ; U1.K21 v2(52.9,33.28) ; U20.8 26.4,54.64 v9(26.15,54.89) ; v2(64.9,28.28) U1.E10 ; U1.AH8 U1.AG8 ; U1.AH8 U1.AH7 ; U1.L20 v2(53.9,34.28) ; v2(59.9,46.28) U1.AB15 ; U1.AG29 v2(44.9,51.28) ; C211.2 83.71,49.74 83.71,49.79 84.21,50.29 v3(84.21,50.53) ; U1.AD31 v2(42.9,48.28) ; U1.AB21 v2(52.9,46.28) ; C282.2 21.92,53.74 v4(22.05,53.62) ; U1.AG6 U1.AH6 ; U1.AH6 U1.AH7 ; v2(63.9,42.28) U1.V11 ; U1.Y21 v2(52.9,44.28) ; U1.T17 v2(56.9,39.28) ; U1.AK23 v2(50.9,54.28) ; U1.P17 v2(56.9,37.28) ; U1.L18 v2(55.9,34.28) ; U1.AL30 v2(43.9,55.28) ; U1.L27 v2(46.9,34.28) ; U1.AG25 v2(48.9,51.28) ; v2(61.9,39.28) U1.T13 ; v2(70.9,24.28) U1.A4 ; U1.Y27 v2(46.9,44.28) ; v2(59.9,51.28) U1.AG15 ; v2(63.9,48.28) U1.AD11 ; v2(64.9,26.28) U1.C10 ; v2(63.9,31.28) U1.H11 ; v2(71.9,53.28) U1.AJ3 ; U1.AJ7 U1.AH7 ; U1.A18 v2(55.9,24.28) ; U1.AA18 v2(55.9,45.28) ; v2(71.9,42.28) U1.V3 ; U1.B17 v2(56.9,25.28) ; U1.G24 v2(49.9,30.28) ; U1.AK30 v2(43.9,54.28) ; v2(65.9,50.28) U1.AF9 ; v2(71.9,51.28) U1.AG3 ; v2(70.9,54.28) U1.AK3 ; U1.C20 v2(53.9,26.28) ; v2(58.9,32.28) U1.J16 ; v3(77.01,34.61) 76.99,34.64 C217.2 ; v2(59.9,31.28) U1.H15 ; v2(67.9,25.28) U1.B7 ; U1.K25 v2(48.9,33.28) ; v3(84.21,46.17) 83.64,46.17 83.43,46.38 83.43,46.98 C216.2 ; U1.F25 v2(48.9,29.28) ; U1.AF18 v2(55.9,50.28) ; U1.E18 v2(55.9,28.28) ; v2(62.9,24.28) U1.A12 ; v3(79.41,46.17) 79.49,46.24 R361.1 ; v2(58.9,30.28) U1.G16 ; U1.V21 v2(52.9,42.28) ; v2(70.9,56.28) U1.AM4 ; v2(71.9,25.28) U1.B3 ; U1.Y17 v2(56.9,44.28) ; v3(78.61,50.53) 78.64,50.5 C212.2 ; v2(63.9,25.28) U1.B11 ; v2(64.9,24.28) U1.A10 ; R289.1 81.65,54.63 80.85,53.83 C206.2 78.94,53.83 78.69,53.58 C214.2 78.09,53.11 v5(77.97,53.24) ; U1.AK19 v2(54.9,54.28) ; U1.D23 v2(50.9,27.28) ; U1.F19 v2(54.9,29.28) ; U1.P27 v2(46.9,37.28) ; v2(58.9,49.28) U1.AE16 ; v2(64.9,30.28) U1.G10 ; v2(60.9,36.28) U1.N14 ; U1.P19 v2(54.9,37.28) ; U1.V19 v2(54.9,42.28) ; U1.A22 v2(51.9,24.28) ; U1.N18 v2(55.9,36.28) ; U1.F23 v2(50.9,29.28) ; U1.M17 v2(56.9,35.28) ; v2(63.9,50.28) U1.AF11 ; U1.N22 v2(51.9,36.28) ; v2(68.9,53.28) U1.AJ6 ; U1.H25 v2(48.9,31.28) ; v2(69.9,53.28) U1.AJ5 ; U1.N26 v2(47.9,36.28) ; U1.AK27 v2(46.9,54.28) ; U1.AJ24 v2(49.9,53.28) ; C110.2 81.01,32.7 C264.2 81.64,33.64 v3(81.81,33.81) ; v3(77.01,28.21) 77.01,28.87 76.31,29.57 R339.1 ; v2(65.9,53.28) U1.AJ9 ; U1.AC22 v2(51.9,47.28) ; v2(61.9,48.28) U1.AD13 ; v2(60.9,47.28) U1.AC14 ; U1.AM24 v2(49.9,56.28) ; U1.C24 v2(49.9,26.28) ; v2(64.9,48.28) U1.AD10 ; U1.AA24 v2(49.9,45.28) ; v2(68.9,24.28) U1.A6 ; U1.A24 v2(49.9,24.28) ; U1.K31 v2(42.9,33.28) ; v2(69.9,51.28) U1.AG5 ; v2(66.9,37.28) U1.P8 ; U1.AG17 v2(56.9,51.28) ; v2(58.9,36.28) U1.N16 ; U1.AM22 v2(51.9,56.28) ; v2(62.9,53.28) U1.AJ12 ; v2(67.9,54.28) U1.AK7 ; U1.AG28 U1.AH28 U1.AH29 U1.AJ29 v2(44.9,53.28) ; v2(62.9,41.28) U1.U12 ; U1.R26 v2(47.9,38.28) ; U1.AD17 v2(56.9,48.28) ; U1.AG23 v2(51.9,51.28) ; v2(58.9,38.28) U1.R16 ; U1.H27 v2(46.9,31.28) ; U1.W22 v2(51.9,43.28) ; v2(63.9,44.28) U1.Y11 ; v2(60.9,38.28) U1.R14 ; U1.W20 v2(53.9,43.28) ; v2(61.9,42.28) U1.V13 ; v2(72.9,46.28) U1.AB2 ; v2(62.9,32.28) U1.J12 ; v2(59.9,35.28) U1.M15 ; U1.J26 v2(47.9,32.28) ; v2(68.9,33.28) U1.K6 ; U1.C18 v2(55.9,26.28) ; U1.K23 v2(50.9,33.28) ; v2(61.9,27.28) U1.D13 ; v2(58.9,26.28) U1.C16 ; U1.F21 v2(52.9,29.28) ; U1.AE18 v2(55.9,49.28) ; v2(60.9,24.28) U1.A14 ; U1.T23 v2(50.9,39.28) ; v2(71.9,33.28) U1.K3 ; v2(66.9,24.28) U1.A8 ; v2(61.9,31.28) U1.H13 ; v2(61.9,33.28) U1.K13 ; v2(72.9,53.28) U1.AJ2 ; v2(62.9,30.28) U1.G12 ; U1.K19 v2(54.9,33.28) ; v2(60.9,26.28) U1.C14 ; v2(59.9,56.28) U1.AM14 ; v2(67.9,24.28) U1.A7 ; v2(59.9,48.28) U1.AD15 ; U1.T28 v2(45.9,39.28) ; v2(60.9,34.28) U1.L14 ; v2(70.9,29.28) U1.F4 ; U1.G20 v2(53.9,30.28) ; v2(66.9,56.28) U1.AM8 ; U1.D21 v2(52.9,27.28) ; v2(62.9,26.28) U1.C12 ; v2(58.9,43.28) U1.W16 ; v2(58.9,47.28) U1.AC16 ; v2(61.9,44.28) U1.Y13 ; U1.M23 v2(50.9,35.28) ; U1.V26 v2(47.9,42.28) ; v2(61.9,37.28) U1.P13 ; U1.AJ30 v2(43.9,53.28) ; v2(63.9,33.28) U1.K11 ; v2(73.9,53.28) U1.AJ1 ; U1.N24 v2(49.9,36.28) ; U1.AM28 v2(45.9,56.28) ; U1.H21 v2(52.9,31.28) ; U1.E20 v2(53.9,28.28) ; v2(62.9,56.28) U1.AM12 ; v2(59.9,27.28) U1.D15 ; U1.AE20 v2(53.9,49.28) ; U1.E26 v2(47.9,28.28) ; U1.AK25 v2(48.9,54.28) ; v2(60.9,32.28) U1.J14 ; U1.W24 v2(49.9,43.28) ; v2(61.9,29.28) U1.F13 ; U1.P31 v2(42.9,37.28) ; v2(70.9,55.28) U1.AL3 ; C263.2 80.76,49.52 R189.1 79.74,49.55 79.41,49.88 v3(79.41,50.53) ; v2(60.9,30.28) U1.G14 ; U1.C22 v2(51.9,26.28) ; U1.R31 v2(42.9,38.28) ; v2(63.9,29.28) U1.F11 ; U1.B25 v2(48.9,25.28) ; v2(69.9,46.28) U1.AB5 ; v2(64.9,56.28) U1.AM10 ; v2(65.9,54.28) U1.AK9 ; C219.2 78.64,27.39 v3(78.61,27.41) ; U1.AK21 v2(52.9,54.28) ; v2(58.9,28.28) U1.E16 ; U1.G26 v2(47.9,30.28) ; U1.D17 v2(56.9,27.28) ; v2(64.9,25.28) U1.B10 ; U1.L26 v2(47.9,34.28) ; v2(57.9,56.28) U1.AM16 ; U1.G18 v2(55.9,30.28) ; U1.W18 v2(55.9,43.28) ; U1.J22 v2(51.9,32.28) ; v2(70.9,50.28) U1.AF4 ; U1.P23 v2(50.9,37.28) ; v2(61.9,46.28) U1.AB13 ; U1.AD21 v2(52.9,48.28)
  TOP w0.381: v4(18.69,17.93) 18.69,18.53 18.39,18.73
  TOP w0.508: v5(27.55,46.51) 27.93,46.12 U8.4 ; v2(71.9,56.28) U1.AM3 ; TP55.1 16.69,29.81 TP41.1 15.25,30.12 14.74,30.63 v5(14.74,31.56) ; 14.59,21.11 13.87,21.11 C135.2 ; v4(14.59,9.87) 13.39,11.07 TP45.1 ; 20.82,19.71 22.02,18.5 v4(22.02,17.93) ; v2(73.9,25.28) U1.B1 ; 20.23,24.35 20.23,23.7 ; 14.4,19.64 13.66,18.91 v4(13.66,17.93) ; v2(73.9,54.28) U1.AK1 ; C51.2 83.13,10.7 83.4,10.44 v4(83.4,9.29) ; v2(71.9,55.28) U1.AL2 ; C130.2 v5(88.38,8.41) ; U1.C32 v2(41.9,26.28) ; v2(73.9,26.28) U1.C1 ; v5(7.1,52.73) 8.28,52.73 C243.2 8.5,51.84 8.12,51.46 v5(7.1,51.46) ; U1.AM31 v2(42.9,56.28) ; C87.2 R32.2 23.01,42.35 v5(22.97,42.31) ; v2(72.9,24.28) U1.A2 ; v4(14.17,25.3) 14.17,24.06 14.59,23.65 ; v4(19.67,10.12) 19.29,10.5 TP49.1 ; U1.AL32 v2(41.9,55.28) ; v2(73.9,55.28) U1.AL1 ; U1.A30 v2(43.9,24.28) ; U1.AK32 v2(41.9,54.28) ; R152.2 76.66,13.52 v5(76.31,13.87) ; U1.B31 v2(42.9,25.28) ; v5(40.25,53.74) 40.12,53.62 C83.2 C24.2 ; v8(72.9,56.28) U1.AM2 ; U15.4 v4(27.22,32.15) ; U1.AL31 v2(42.9,55.28) ; U1.AM30 v2(44.9,56.28) ; U1.A31 v2(42.9,24.28) ; v5(7.1,37.74) 8.12,37.74 8.5,38.12 C242.2 8.28,39.01 v5(7.1,39.01) ; v2(71.9,24.28) U1.A3 ; C143.2 v5(43.55,22.63) ; U1.B32 v2(41.9,25.28)
  BOTTOM w0.127: R49.2 34.73,36.18 R55.2 33.9,37.53 33.88,37.54 33.88,38.11 v3(33.46,38.53)
  BOTTOM w0.147: R47.2 30.05,37.02 29.58,37.49 29.58,38.21 R56.2
  BOTTOM w0.203: R18.2 23.48,46.38 v5(23.23,46.63) ; 8.5,47.65 8.92,48.07 v5(10.93,48.07) ; 8.5,47.65 8.08,48.07 7.76,48.07 7.42,48.41 7.4,48.41 R375.2 ; 8.5,47.65 C285.2 ; v9(25.13,25.93) 25.48,26.27 R59.2 ; v4(85.28,16.81) 84.98,16.51 84.98,16.32 C128.2 ; v9(5.07,45.11) 4.82,44.86 U21.8 ; v3(33.57,31.93) 30.82,31.93 30.59,32.15 30.59,33.68 30.85,33.93 31.48,33.93 31.78,34.22 R58.2 31.78,35.25 R57.2 ; R32.2 23.44,42.35 v5(22.97,42.31) ; v4(85.28,17.78) 85.34,17.71 R4.1 86.18,17.71 86.73,17.17 86.73,16.32 C31.2 86.44,15.01 C205.2 ; v2(44.9,47.28) R16.2 ; TP39.1 v9(33.01,19.45)
  BOTTOM w0.254: U1.AJ3 71.4,52.78 v2(71.9,53.28) ; v2(46.9,44.28) C272.2 ; J4.125 v5(14.74,36.64) ; U19.D1 v3(77.01,34.61) ; J4.148 v5(16.01,32.83) ; C165.2 84.28,17.74 v4(84.32,17.78) ; v2(72.9,53.28) 72.4,52.78 U1.AJ2 ; J4.91 v5(17.28,41.72) ; J4.71 v5(13.47,45.53) ; v9(49.5,19.14) 49.3,18.93 U5.37 ; v2(63.9,51.28) U1.AH11 ; J4.110 v5(13.47,39.18) ; J4.1 v5(19.82,55.69) ; C44.2 v2(56.9,39.28) ; TP69.1 20.04,26.58 v4(20.04,25.49) ; U19.T9 v3(87.53,27.35) ; U1.C12 62.4,26.78 v2(62.9,26.28) ; J4.42 v5(18.55,49.34) ; C118.2 30.59,27.87 v4(30.59,26.6) ; J4.95 v5(12.2,41.72) ; U18.M1 v3(84.21,46.17) ; U17.E8 v3(77.81,51.33) ; U17.D8 v3(77.01,51.33) ; J4.24 v5(10.93,53.15) ; R45.2 R46.2 v2(43.9,43.28) ; 72.23,14.53 U6.23 ; U18.P1 v3(85.81,46.17) ; J4.157 v5(14.74,31.56) ; 71.73,14.53 U6.24 ; U17.B9 v3(75.41,50.53) U17.A9 ; J4.31 v5(12.2,51.88) ; U1.AB2 72.4,45.78 v2(72.9,46.28) ; v9(50.88,20.13) 51.13,20.39 U5.5 ; R376.2 8.5,41.01 8.88,41.39 8.88,42.57 9.3,42.99 v5(10.93,42.99) J4.88 ; J4.39 v5(12.2,50.61) ; U17.M9 v3(84.21,50.53) ; U17.B1 v3(75.41,57.73) ; C270.2 v2(44.9,51.28) ; J4.78 v5(13.47,44.26) ; v2(71.9,42.28) 71.4,41.78 U1.V3 ; 70.23,14.53 U6.27 ; U19.B9 v3(75.41,27.41) U19.A9 ; U18.B1 v3(75.41,46.17) ; U18.E8 v3(77.81,39.77) ; J4.101 v5(14.74,40.45) ; C187.2 U1.AE10 v2(64.9,49.28) 65.4,49.78 U1.AF9 ; v2(68.9,42.28) C190.2 ; C269.2 U1.V25 v2(48.9,42.28) ; 53.63,14.53 U5.21 54.08,15.24 ; C12.2 63.26,23.76 63.26,23.92 v2(62.9,24.28) ; C57.2 40.51,27.3 39.54,28.27 39.54,29.09 C121.2 ; v2(43.9,52.28) 44.4,51.78 U1.AH30 ; J4.46 v5(13.47,49.34) ; J4.59 v5(17.28,46.8) ; U18.T9 v3(87.41,38.97) ; U19.T1 v3(87.47,34.67) ; J4.108 v5(16.01,39.18) ; v2(56.9,42.28) 56.91,42.28 C5.2 ; C13.2 57.81,27.28 v2(56.9,27.28) ; C41.2 v2(56.9,54.28) ; U19.G8 v3(79.41,28.21) ; C176.2 v2(50.9,27.28) ; J4.150 v5(13.47,32.83) ; U19.P9 v3(85.81,27.41) ; v2(47.9,28.28) U1.E26 C167.2 ; R407.2 v2(42.9,33.28) C74.2 ; C79.2 U1.A26 v2(47.9,24.28) ; v2(52.9,33.28) C175.2 ; U19.M9 v3(84.21,27.41) ; v2(55.9,50.28) C102.2 ; U18.A9 v3(75.41,38.97) U18.B9 ; U6.18 74.64,16.93 ; v2(63.9,49.28) U1.AE11 ; U17.G1 v3(79.41,57.73) ; C275.2 48.4,45.78 v2(47.9,45.28) ; J4.89 v5(21.09,41.72) ; U1.AD15 v2(59.9,48.28) ; v9(70.47,20.13) 70.73,20.39 U6.5 ; R320.1 U1.R26 v2(47.9,38.28) ; v2(44.9,36.28) C86.2 ; C89.2 v2(61.9,51.28) C90.2 ; 73.67,15.24 U6.21 73.23,14.53 ; J4.65 v5(19.82,45.53) ; U1.AJ18 v2(55.9,53.28) ; J4.27 v5(17.28,51.88) ; v2(47.9,47.28) C276.2 ; J4.118 v5(13.47,37.91) ; U18.P9 v3(85.81,38.97) ; J4.29 v5(14.74,51.88) ; C25.2 47.4,33.78 v2(46.9,34.28) ; C101.2 v2(56.9,51.28) ; v2(69.9,24.28) 69.84,24.22 C202.2 ; 69.73,14.53 U6.28 ; C30.2 v2(58.9,49.28) ; v2(48.9,46.28) U1.AC26 ; U17.E2 v3(77.81,56.93) ; v2(54.9,39.28) 54.44,39.74 54.44,39.91 C10.2 ; v2(58.9,34.28) 58.58,34.61 57.92,34.61 C7.2 ; J4.131 v5(17.28,35.37) ; U6.16 74.64,17.93 ; J4.12 v5(16.01,54.42) ; v2(53.9,28.28) 54.4,28.78 U1.E20 ; R322.1 U1.AF26 v2(47.9,50.28) ; C194.2 v2(66.9,46.28) U1.AB8 ; U18.J2 v3(81.81,45.37) ; C273.2 U1.T28 v2(45.9,39.28) ; J4.112 v5(10.93,39.18) ; U18.J8 v3(81.81,39.77) ; v2(50.9,48.28) C92.2 ; 55.04,15.93 U5.20 54.33,15.49 ; U5.18 55.04,16.93 ; 51.63,14.53 U5.25 ; v2(60.9,26.28) 60.4,26.78 U1.C14 ; 73.93,15.49 U6.20 74.64,15.93 ; C40.2 U1.AG23 v2(51.9,51.28) ; v2(68.9,33.28) 69.26,32.92 R124.1 ; U19.E1 v3(77.81,34.61) ; U17.T9 v3(87.41,50.53) ; C178.2 52.4,45.78 v2(51.9,45.28) ; 52.63,14.53 U5.23 ; v2(50.9,46.28) 50.4,46.78 C93.2 ; U5.19 55.04,16.43 ; v2(52.9,27.28) C174.2 ; U19.J8 v3(81.81,28.21) ; R186.1 v2(63.9,33.28) ; C3.2 57.45,31.28 v2(56.9,31.28) ; J4.76 v5(16.01,44.26) ; U18.T1 v3(87.41,46.17) ; R408.2 43.19,29.58 v2(42.9,29.28) ; J4.67 v5(17.28,45.53) ; U17.D1 v3(77.01,57.73) ; C27.2 47.4,36.78 v2(46.9,37.28) ; v2(63.9,46.28) U1.AB11 ; J4.103 v5(12.2,40.45) ; U19.B1 v3(75.41,34.61) ; J4.86 v5(13.47,42.99) ; 70.73,14.53 U6.26 ; C193.2 v2(69.9,46.28) ; J4.20 v5(16.01,53.15) ; U17.P1 v3(85.81,57.73) ; v3(84.21,35.46) 83.81,35.06 U19.M1 ; U19.J2 v3(81.81,33.81) ; v2(50.9,29.28) C200.2 ; C278.2 66.32,52.7 v2(66.9,53.28) ; J4.54 v5(13.47,48.07) ; U6.17 74.64,17.43 ; 51.13,14.53 U5.26 ; U17.F9 v3(78.61,50.53) ; J4.116 v5(16.01,37.91) ; 53.13,14.53 U5.22 ; U18.D8 v3(77.01,39.77) ; U1.H13 61.4,31.78 v2(61.9,31.28) ; C268.2 48.4,42.78 v2(47.9,42.28) ; 78.5,14.34 v4(79.24,14.34) 79.24,13.55 ; v2(63.9,44.28) R283.1 ; C122.2 33.93,31.56 v3(33.57,31.93) ; v2(66.9,56.28) 66.45,55.83 C279.2 ; v2(63.9,39.28) 63.73,39.46 63.73,39.65 C1.2 ; U18.E2 v3(77.81,45.37) ; J4.74 v5(18.55,44.26) ; v2(54.9,31.28) C9.2 ; J4.23 v5(12.2,53.15) J4.15 ; J4.97 v5(21.09,40.45) ; v2(55.9,45.28) C162.2 ; J4.35 v5(17.28,50.61) ; U19.G9 v3(79.41,27.41) ; J4.3 v5(17.28,55.69) ; 72.73,14.53 U6.22 ; C77.2 v2(54.9,46.28) ; C203.2 49.35,23.74 v2(49.9,24.28) 50.14,24.04 50.14,23.97 50.24,23.87 C204.2 ; J4.135 v5(12.2,35.37) ; U19.F9 v3(78.61,27.41) ; v9(69.1,19.14) 68.9,18.93 U6.37 ; v2(48.9,39.28) R321.1 ; U18.M9 v3(84.21,38.97) ; v2(63.9,37.28) R187.1 ; v2(48.9,44.28) C271.2 ; J4.37 v5(14.74,50.61) ; v2(65.9,50.28) C195.2 ; 80.51,13.55 v4(80.51,14.34) ; v2(68.9,24.28) 68.95,24.23 C201.2 ; J4.121 v5(19.82,36.64) ; J4.159 v5(12.2,31.56) ; 81.9,13.55 v4(81.9,14.34) ; J4.93 v5(14.74,41.72) ; U18.D1 v3(77.01,46.17) ; v2(59.9,44.28) U1.AA14 ; J4.44 v5(16.01,49.34) ; U19.E2 v3(77.81,33.81) ; U18.B3 v3(76.21,43.77) ; J4.52 v5(16.01,48.07) ; C91.2 v2(59.9,51.28) 60.4,51.78 C38.2 ; J4.69 v5(14.74,45.53) ; J4.133 v5(14.74,35.37) ; 52.13,14.53 U5.24 ; U17.G8 v3(79.41,51.33) ; C85.2 v5(23.23,51.08) ; U18.E1 v3(77.81,46.17) ; v2(64.9,48.28) C116.2 ; J4.57 v5(19.82,46.8) ; J4.140 v5(16.01,34.1) ; J4.25 v5(19.82,51.88) ; U18.F9 v3(78.61,38.97) ; J4.7 v5(13.47,55.69) ; J4.10 v5(18.55,54.42) ; J4.120 v5(10.93,37.91) ; C14.2 58.86,24.24 v2(58.9,24.28) 58.9,23.57 C11.2 ; J4.50 v5(18.55,48.07) ; U17.J8 v3(81.81,51.33) ; U17.P9 v3(85.81,50.53) ; U19.B3 v3(75.41,33.01) ; v2(53.9,49.28) C103.2 ; J4.80 v5(10.93,44.26) 10.5,43.83 C283.2 ; U17.T1 v3(87.41,57.73) ; U1.AD21 v2(53.9,47.28) ; J4.127 v5(12.2,36.64) ; U18.G9 v3(79.41,38.97) ; J4.18 v5(18.55,53.15) ; v2(62.9,41.28) U1.V11 ; 71.23,14.53 U6.25 ; U6.19 74.64,16.43 ; J4.22 v5(13.47,53.15) ; U17.E1 v3(77.81,57.73) ; U17.G9 v3(79.41,50.53) ; U19.D8 v3(77.01,28.21) ; J4.48 v5(10.93,49.34) ; J4.99 v5(17.28,40.45) ; J4.138 v5(18.55,34.1) ; v2(61.9,46.28) U1.AC12 ; v4(31.86,40.32) 31.7,40.16 30.34,40.16 30.05,39.86 C120.2 30.05,38.71 R56.2 ; v2(60.9,53.28) C39.2 ; C26.2 v2(47.9,36.28) ; U19.P1 v3(85.81,34.61) ; v2(54.9,25.28) C173.2 ; J4.56 v5(10.93,48.07) ; J4.84 v5(16.01,42.99) ; v2(63.9,31.28) C177.2 ; 50.13,14.53 U5.28 ; J4.106 v5(18.55,39.18) ; C4.2 50.9,40.1 v2(50.9,39.28) ; U18.G8 v3(79.41,39.77) ; v2(46.9,49.28) C277.2 ; C172.2 v2(49.9,45.28) ; U17.J2 v3(81.81,56.93) ; J4.63 v5(13.47,46.8) ; v2(63.9,42.28) C196.2 ; U18.G1 v3(79.41,46.17) ; J4.33 v5(19.82,50.61) ; J4.114 v5(19.82,37.91) ; J4.142 v5(13.47,34.1) ; v2(61.9,29.28) C199.2 ; J4.123 v5(17.28,36.64) ; v2(49.9,50.28) R319.1 ; U5.17 55.04,17.43 ; v2(56.9,46.28) C28.2 ; U19.G1 v3(79.41,34.61) ; v2(52.9,48.28) C171.2 ; J4.61 v5(14.74,46.8) ; U5.16 55.04,17.93 ; 50.63,14.53 U5.27 ; U17.B3 v3(76.21,55.33) ; U19.E8 v3(77.81,28.21) ; U17.M1 v3(84.21,57.73) ; v2(63.9,25.28) C80.2 ; J4.144 v5(10.93,34.1) ; v2(59.9,31.28) C163.2 ; J4.82 v5(18.55,42.99) ; v2(55.9,49.28) C43.2
  BOTTOM w0.508: v4(31.86,40.32) 31.86,40.63 R149.1 ; v2(52.9,51.28) 52.83,51.36 C281.2 ; C36.2 35.08,53.66 v9(35.17,53.74) ; C84.2 34.87,50.91 v9(35.17,51.2) ; C68.2 71.9,25.55 v2(71.9,25.28) ; C123.2 v5(27.8,27.46) ; 27.67,39.14 v5(27.67,37.49) ; v2(68.9,33.28) 68.9,34.11 68.41,34.59 C67.2 ; v2(51.9,56.28) 51.93,56.25 C280.2 ; v2(64.9,24.28) 64.62,24 64.62,22.21 C58.2
  vias: v3(38.62,38.35) v3(78.32,36.78) v3(79.41,37.04) v3(81.61,30.5) v4(12.22,18.11) v4(12.88,25.21) v4(17.01,22.25) v4(17.01,21.8) v4(17.01,21.36) v4(17.01,20.92) v4(17.45,22.25) v4(17.45,21.8) v4(17.45,21.36) v4(17.45,20.92) v4(17.89,22.25) v4(17.89,21.8) v4(17.89,21.36) v4(17.89,20.92) v4(18.34,22.25) v4(18.34,21.8) v4(18.34,21.36) v4(18.34,20.92) v4(18.78,16.91) v4(21.45,25.3) v4(23.36,17.89) v4(24.75,21.23) v4(26.42,19.23) v4(28.6,21.11) v4(28.69,29.93) v4(29.41,17.55) v4(33.26,26.6) v4(34.49,16.28) v4(35.93,26.6) v4(38.6,26.6) v4(39.67,23.9) v4(40.63,27.07) v4(45.71,4.09) v4(46.68,20.51) v4(50.38,7.01) v4(52.29,7.01) v4(52.69,10.98) v4(62.53,12.63) v4(63.97,6.12) v4(63.97,4.09) v4(66.28,20.51) v4(67.17,9.55) v4(68.1,6.75) v4(68.57,5.61) v4(68.57,3.71) v4(79.59,4.85) v4(79.62,5.87) v4(79.62,3.71) v4(85.33,10.69) v4(86.35,11.71) v4(87.36,10.69) v5(51.63,14.27) v5(52.94,56.95) v5(53.84,10.56) v5(53.84,8.02) v5(53.84,5.51) v5(54.22,14.37) v5(55.11,57.02) v5(55.11,10.56) v5(55.11,5.51) v5(55.36,15.52) v5(55.36,14.37) v5(56.5,15.52) v5(56.5,14.37) v5(57.14,57.03) v5(57.65,15.52) v5(61.07,59.21) v5(62.98,59.33) v5(64.88,59.21) v5(71.23,13.87) v5(72.5,13.87) v5(73.77,13.87) v5(75.04,15.14) v5(75.04,13.87) v5(83.43,8.02) v7(55.11,8.02) v9(6.34,45.11) v9(24.88,54.89) v9(26.4,25.93) v9(33.01,21.99) v9(33.01,20.72) v9(34.28,21.99) v9(34.28,20.72) v9(34.28,19.45) v9(35.17,52.47) v9(35.55,21.99) v9(35.55,20.72) v9(35.55,19.45) v9(36.44,53.74) v9(36.44,52.47) v9(49.5,20.13) v9(50.88,19.14) v9(69.1,20.13) v9(70.47,19.14) v9(85.33,11.71) v9(86.35,10.69) v9(87.36,11.71)
VDD_1.2V: length 58.1
  TOP w0.203: TP48.1 7.1,26.57 8.37,26.57 9.26,25.68 9.51,25.68 ; R79.2 v5(39.48,27.33) ; U9.29 14.03,22.81
  TOP w0.254: R84.2 29.03,26.6 v5(28.94,26.69) ; R94.2 R90.2 v5(35.04,27.33) ; R77.2 R78.2 v5(37.71,27.33) ; U1.AF29 v2(44.9,50.28) ; R92.2 R93.2 v5(32.37,27.33) ; U1.AF28 v2(45.9,50.28)
  BOTTOM w0.254: v5(28.94,26.69) 28.94,28.09 29.45,28.6 29.45,31.77 28.44,32.79 28.44,39.77 30.12,41.46 30.12,44.46 30,44.59 30,46.17 30.46,46.63 30.47,46.63 30.85,47.01 30.85,48.67 31.22,49.05 31.99,49.05 32.75,49.81 36.44,49.81 37.45,50.82 37.45,52.35 38.21,53.11 40.63,53.11 41.07,52.67 41.07,51.03 41.32,50.78 42.1,50.78 42.19,50.7 42.28,50.7 42.53,50.44 42.53,50.06 42.79,49.81 44.42,49.81 v2(44.9,50.28) ; v2(45.9,50.28) C270.1 45.4,50.78 v2(44.9,50.28) ; C274.1 44.9,50.28 v2(44.9,50.28)
  vias: v5(11.99,25.68) v7(11.99,24.41) v7(11.99,23.14)
VDD_1.5V: length 2.3
  TOP w0.203: U9.3 v5(16.84,20.24)
  TOP w0.508: v5(10.78,13.99) 10.66,13.87 TP46.1
  vias: v4(41.01,34.35) v4(41.03,32.41) v5(10.78,16.53) v5(10.78,15.39)
VDD_1.8V: length 25.9
  TOP w0.203: U9.7 v5(18.44,20.24)
  TOP w0.254: U1.U27 v2(46.9,41.28) ; U1.U26 v2(47.9,41.28)
  TOP w0.508: TP50.1 v4(20.94,12.91)
  BOTTOM w0.254: 46.4,59.28 46.39,59.28 46.39,57.3 45.83,57.3 45.4,56.87 45.4,56.03 45.53,55.9 45.53,54.13 45.4,54 45.4,52.91 46.22,52.09 46.22,51.2 46.39,51.03 46.39,41.79 v2(46.9,41.28) ; v2(46.9,41.28) 47.18,41 47.61,41 v2(47.9,41.28) C269.1 ; v2(46.9,41.28) C273.1
  vias: v1(37.71,59.97) v1(69.84,57.68) v4(19.67,12.91) v4(20.31,16.79) v5(1.9,24.28) v7(1.9,23.28)
VDD_3.3V: length 116.7
  TOP w0.203: 20.55,22.81 U9.17 ; v5(9.89,41.68) 10.49,41.08 21.41,41.08 22.5,39.99 U15.8
  TOP w0.254: R393.2 22.85,51.46 22.59,51.2 ; U1.W26 v2(47.9,43.28) ; U1.V27 v2(46.9,42.28) ; U1.Y26 v2(47.9,44.28) ; U1.AA27 v2(46.9,45.28) ; U1.AB26 v2(47.9,46.28) ; U1.AD27 v2(46.9,48.28)
  TOP w0.508: v4(66.28,22.29) 60.53,22.29 59.55,23.26 50.91,23.26 50.55,23.62 48.02,23.62 v4(46.68,22.29) ; 21.04,22.81 20.55,22.81 ; L20.2 21.31,28.66 20.43,29.53 TP56.1 20.88,30.38 R68.1 21.79,31.01 R34.2 ; v4(27.67,42.35) 26.44,42.35 R22.1 26.36,42.35 v4(25.13,42.35) 24.88,42.35 24.73,42.2 24.72,42.2 24.5,41.98 24.5,41.97 24.08,41.55 C87.1 23.41,41.1 U15.8 23.41,38.43 23.1,38.12 23.1,36.35 v5(23.86,35.58) ; 22.59,51.2 22.59,50.06 23.1,49.55 v4(24.12,49.55)
  04_SIG w0.254: v2(41.9,49.28) 44.07,49.28 44.56,48.79 46.34,48.79 46.85,48.28 v2(46.9,48.28)
  BOTTOM w0.203: v2(43.9,33.28) 44.4,33.78 R365.2 ; v5(22.85,26.57) 23.48,26.57 24.88,27.96 R89.2
  BOTTOM w0.254: v2(46.9,42.28) C268.1 ; C276.1 v2(47.9,46.28) C275.1 ; v2(41.9,49.28) 42.4,48.78 R42.1 R41.1 43.4,48.69 43.52,48.81 43.52,48.86 R405.1 ; v2(47.9,44.28) 48.4,44.78 C272.1 ; v2(47.9,43.28) C271.1 ; R406.1 v2(43.9,33.28) R19.1 ; C85.1 24.57,50.28 24.75,50.46 24.75,50.95 24.92,51.12 R25.1 R26.1 R27.1 28.18,51.12 28.52,51.12 29.03,50.61 R404.1 R43.1 ; v2(46.9,48.28) 47.4,48.78 C277.1 ; R394.2 6.85,40.54 7.23,40.16 9.13,40.16 9.89,40.92 v5(9.89,41.68)
  BOTTOM w0.508: v5(23.86,35.58) U7.8 R28.1 23.61,31.94 23.23,31.56 23.23,30.68 23.27,30.64 23.27,28.13 22.85,27.71 v5(22.85,26.57) ; R30.1 R24.1 R31.1 ; R31.1 26.66,47.14 26.49,47.31 R403.1 R44.1 25.98,48.92 24.5,48.92 24.12,49.3 v4(24.12,49.55) C85.1 ; R31.1 27.13,45.65 28.05,44.73 28.05,44.46 28.69,43.83 28.69,42.86 28.18,42.35 v4(27.67,42.35) R29.1
  vias: v4(21.45,23.73) v4(24.24,22.69) v4(26.91,22.69) v5(22.85,25.3)
VDD_5.0V: length 101.3
  TOP w0.203: 14.34,21.99 14.36,22.01 U9.31 ; R98.2 v5(7.35,25.8) ; U9.24 17.24,24.52 v5(17.24,24.59) ; 18.84,24.6 U9.20 ; U9.4 17.24,18.08 v4(17.09,17.93) ; U9.2 16.44,18.89 16.24,18.69 ; U9.21 18.44,23.25 v5(18.64,22.99) ; U9.25 v5(16.84,22.99) ; R104.2 v5(8.24,25.8) ; U9.26 16.44,24.63 ; 19.77,18.82 19.04,18.82 18.84,19.02 U9.8
  TOP w0.381: v5(19.8,18.79) 19.77,18.82 19.73,18.79
  TOP w0.508: v5(51.8,4.98) 51.8,4.44 C182.1 50.53,4.44 v5(50.53,4.98) ; L21.2 61.2,9.37 61.2,10.05 62.53,11.38 R411.2 ; TP42.1 16.37,27.16 v5(15.77,26.57) ; 13.21,22.01 C135.1 v5(12.32,22.03) ; 18.84,24.6 18.84,24.73 18.84,25.26 v4(18.62,25.49) ; R180.2 v4(39.93,21.73)
  03_SIG w0.508: v4(68.95,22.77) 68.95,23.01 68.57,23.39 49.77,23.39 49.35,22.97 v4(49.35,22.77)
  04_SIG w0.508: 75.68,12.85 75.3,12.47 72.63,12.47 72.59,12.43 69.13,12.43 v4(68.82,12.13) ; 75.68,12.85 77.08,12.85 77.71,13.49 85.59,13.49 86.22,14.12 v5(86.22,19.58) ; 75.68,12.85 75.68,15.4 75.3,15.78 75.3,18.57 73.01,20.85 73.01,22.5 72,23.52 69.7,23.52 v4(68.95,22.77) ; v4(39.93,21.73) 40.12,21.61 40.63,21.11 42.79,21.11 43.17,21.49 47.19,21.49 48.48,22.77 v4(49.35,22.77)
  BOTTOM w0.203: v4(68.95,22.77) 68.61,23.11 68.6,23.11 68.15,23.56 R126.1
  BOTTOM w0.254: C204.1 50.16,22.77 v4(49.35,22.77) ; v4(49.35,22.77) 49.35,22.79 49.06,23.09 48.99,23.09 48.52,23.56 R74.1 ; v4(49.35,22.77) 49.35,22.02 49.63,21.74 U5.2 ; U6.2 69.23,22.12 68.95,22.4 v4(68.95,22.77) C202.1
  BOTTOM w0.508: v5(86.22,19.58) 85.46,19.58 84.91,19.04 R331.1
  vias: v4(15.27,17.93) v4(15.77,25.3) v4(20.42,17.93) v5(11.3,22.03) v5(15.27,17.04) v5(16.37,17.04) v5(17.26,25.47) v5(59.55,10.44) v5(59.55,9.17) v5(59.55,7.9) v5(59.55,6.63) v5(59.55,5.36) v5(59.55,4.09)
VDD_5.0V_EN: length 73.8
  TOP w0.147: U13.9 v5(67.41,11.09) ; TP67.1 v5(69.96,3.96)
  02_GND w0.127: v3(30.09,34.49) 31.04,34.47 31.23,34.28 U2.J13
  03_SIG w0.121: v2(45.9,31.28) 45.41,31.77 42.79,31.77 41.52,33.04 41.52,34.47 41.39,34.6 41.39,35.34 41.73,35.69 41.87,35.69 42.3,36.12 42.3,36.45 42.07,36.69 41.6,36.69 40.38,35.47 38.22,35.47 37.98,35.71 31.86,35.71 30.64,34.49 v3(30.09,34.49)
  07_SIG w0.121: v5(67.41,11.09) 68.44,10.06 68.44,8.41 69.96,6.88 v5(69.96,3.96)
  08_SIG w0.121: v2(45.9,31.28) 46.3,30.88 46.3,27.04 46.09,26.82 46.09,24.36 46.38,24.07 46.38,23.73 46.22,23.57 46.22,20.22 46.98,19.45 46.98,15.9 50.66,12.22 v4(51.08,12.22) 61.07,12.22 61.93,13.08 65.42,13.08 v5(67.41,11.09)
VDD_5.0V_PGOOD: length 60.4
  TOP w0.147: U13.8 68.02,11.11 67.93,11.2 R99.1
  02_GND w0.127: v3(38.6,30.5) 38.13,30.55 U2.C2
  08_SIG w0.121: v4(67.93,11.82) 67.93,10.95 67.42,10.44 65.9,10.44 65.27,9.8 59.17,9.8 58.53,9.17 49.01,9.17 48.62,9.56 38.33,9.56 37.71,10.18 v4(36.44,10.18) 36.44,11.07 36.9,11.53 36.9,15.16 35.96,16.1 35.96,16.98 35.75,17.18 35.75,17.96 35.75,18.38 36.9,19.52 36.9,20.05 37.13,20.29 37.13,20.87 37.45,21.19 37.45,22.88 38.15,23.59 38.15,23.85 38.9,24.6 38.9,24.6 39.16,24.86 39.16,25.23 39.09,25.3 39.09,26.31 39.93,27.15 39.93,27.51 39.61,27.83 39.61,29.49 v3(38.6,30.5)
VDD_7401_EN: length 55.8
  TOP w0.127: v3(29.27,33.65) 29.69,34.07 30.61,34.07 U2.G14
  TOP w0.147: v5(3.8,23.52) R103.2 3.58,24.24 3.16,24.66 3.16,26.44 TP66.1
  TOP w0.203: U9.30 16.16,22.41 v5(16.27,22.3)
  04_SIG w0.121: v3(29.27,33.65) 28.92,33.3 27.55,33.3 26.15,31.9 23.61,31.9 23.1,31.39 21.2,31.39 20.82,31.01 15.74,31.01 15.35,31.39 15.35,31.77 14.99,32.14 13.18,32.14 12.81,31.77 12.81,30.12 10.91,28.22 10.91,22.76 11.16,22.5 13.7,22.5 13.9,22.3 v5(16.27,22.3)
  07_SIG w0.121: v5(16.27,22.3) 15.2,21.23 8.75,21.23 8.24,21.74 5.58,21.74 v5(3.8,23.52)
VDD_7401_PGOOD: length 55.2
  TOP w0.127: v3(39.41,32.31) 38.99,31.89 38.02,31.89 U2.D1
  TOP w0.147: R100.1 v5(4.69,23.52) 4.18,23.01 3.42,23.01 2.53,23.9 2.53,25.3 TP64.1
  TOP w0.203: v5(14.34,20.34) 14.41,20.41 U9.35
  04_SIG w0.121: v5(30.21,28.47) 29.58,28.47 29.32,28.22 v5(15.1,28.22) ; v5(14.34,20.34) 13.2,21.49 11.16,21.49 8.62,24.03 5.19,24.03 v5(4.69,23.52)
  07_SIG w0.121: v5(30.21,28.47) 30.21,29.23 33.3,32.32 33.83,32.32 34.08,32.58 34.08,32.9 34.34,33.16 34.67,33.16 34.72,33.11 38.08,33.11 38.43,32.75 38.76,32.75 39.2,32.31 v3(39.41,32.31)
  08_SIG w0.121: v5(15.1,28.22) 15.1,21.11 v5(14.34,20.34)
VDD_CORE: length 203.8
  TOP w0.203: R167.1 56.34,21.83 55.87,21.36 55.87,17.8 56.38,17.3 59.4,17.3 L18.2 ; L17.2 64.4,17.3 67.81,17.3 68.06,17.55 68.06,20.6 68.61,21.14 R166.1
  TOP w0.254: v2(60.9,35.28) U1.M14 ; U1.AB22 v2(51.9,46.28) ; v2(58.9,35.28) U1.M16 ; U1.G19 v2(54.9,30.28) ; U1.B20 v2(53.9,25.28) ; U1.R23 v2(50.9,38.28) ; v2(61.9,24.28) U1.A13 ; U1.C25 v2(48.9,26.28) ; U1.F20 v2(53.9,29.28) ; U1.V18 v2(55.9,42.28) ; v2(62.9,27.28) U1.D12 ; U1.R25 v2(48.9,38.28) ; U1.L31 v2(42.9,34.28) ; v2(63.9,45.28) U1.AA11 ; U1.P22 v2(51.9,37.28) ; v2(62.9,29.28) U1.F12 ; U1.J23 v2(50.9,32.28) ; U1.C17 v2(56.9,26.28) ; U1.Y22 v2(51.9,44.28) ; U1.A23 v2(50.9,24.28) ; U1.F24 v2(49.9,29.28) ; U1.U21 v2(52.9,41.28) ; v2(60.9,37.28) U1.P14 ; v2(60.9,29.28) U1.F14 ; v2(60.9,25.28) U1.B14 ; v2(60.9,48.28) U1.AD14 ; U1.C23 v2(50.9,26.28) ; v2(61.9,43.28) U1.W13 ; U1.K18 v2(55.9,33.28) ; v2(59.9,43.28) U1.W15 ; U1.AB18 v2(55.9,46.28) ; U1.D22 v2(51.9,27.28) ; v2(58.9,29.28) U1.F16 ; U1.A21 v2(52.9,24.28) ; U1.AD20 v2(53.9,48.28) ; U1.J17 v2(56.9,32.28) ; U1.AC23 v2(50.9,47.28) ; U1.H26 v2(47.9,31.28) ; U1.W21 v2(52.9,43.28) ; U1.P20 v8(53.9,37.28) ; U1.H24 v2(49.9,31.28) ; U1.T18 v2(55.9,39.28) ; U1.G27 v2(46.9,30.28) ; v2(59.9,45.28) U1.AA15 ; U1.R17 v2(57.9,39.28) ; U1.W25 v2(48.9,43.28) ; U1.L30 v2(43.9,34.28) ; U1.L19 v8(54.9,34.28) ; v2(63.9,38.28) U1.R11 ; v2(63.9,43.28) U1.W11 ; U1.N25 v2(48.9,36.28) ; v2(61.9,28.28) U1.E13 ; v2(60.9,42.28) U1.V14 ; v2(58.9,46.28) U1.AB16 ; U1.AC21 v2(52.9,47.28) ; U1.H20 v2(53.9,31.28) ; v2(62.9,48.28) U1.AD12 ; v2(61.9,45.28) U1.AA13 ; v2(60.9,46.28) U1.AB14 ; v2(63.9,41.28) U1.U11 ; v2(58.9,48.28) U1.AD16 ; U1.N19 v2(54.9,36.28) ; U1.K20 v2(53.9,33.28) ; v2(63.9,32.28) U1.J11 ; v2(62.9,37.28) U1.P12 ; v2(59.9,26.28) U1.C15 ; U1.M22 v2(51.9,35.28) ; U1.D24 v2(49.9,27.28) ; v2(62.9,33.28) U1.K12 ; U1.AE19 v2(54.9,49.28) ; v2(58.9,31.28) U1.H16 ; U1.W23 v2(50.9,43.28) ; U1.V20 v2(53.9,42.28) ; U1.Y20 v2(53.9,44.28) ; U1.N23 v2(50.9,36.28) ; v2(59.9,41.28) U1.U15 ; U1.C21 v2(52.9,26.28) ; v2(61.9,38.28) U1.R13 ; v2(63.9,47.28) U1.AC11 ; U1.B22 v2(51.9,25.28) ; U1.B26 v2(47.9,25.28) ; U1.F22 v2(51.9,29.28) ; U1.L29 v2(44.9,34.28) ; U1.E17 v2(56.9,28.28) ; U1.D18 v2(55.9,27.28) ; v2(58.9,33.28) U1.K16 ; v2(59.9,24.28) U1.A15 ; U1.AD22 v2(51.9,48.28) ; U1.G23 v2(50.9,30.28) ; U1.L17 v2(56.9,34.28) ; v2(59.9,30.28) U1.G15 ; v2(62.9,35.28) U1.M12 ; U1.G25 v2(48.9,30.28) ; v2(59.9,47.28) U1.AC15 ; U1.AA25 v2(48.9,45.28) ; v2(61.9,34.28) U1.L13 ; v2(59.9,28.28) U1.E15 ; U1.C19 v2(54.9,26.28) ; U1.L21 v2(52.9,34.28) ; U1.M26 v2(47.9,35.28) ; U1.E21 v2(52.9,28.28) ; U1.AE17 v2(56.9,49.28) ; v2(58.9,42.28) U1.V16 ; U1.U17 v2(56.9,41.28) ; v2(61.9,32.28) U1.J13 ; U1.V22 v2(51.9,42.28) ; U1.AB24 v2(49.9,46.28) ; v2(62.9,25.28) U1.B12 ; v2(62.9,46.28) U1.AB12 ; v2(58.9,27.28) U1.D16 ; U1.W19 v2(54.9,43.28) ; U1.E25 v2(48.9,28.28) ; U1.T24 v2(49.9,39.28) ; U1.N21 v8(52.9,36.28) ; v2(63.9,34.28) U1.L11 ; U1.AA19 v2(54.9,45.28) ; U1.U25 v2(48.9,41.28) ; v2(58.9,37.28) U1.P16 ; U1.E23 v2(50.9,28.28) ; v2(63.9,28.28) U1.E11 ; U1.M30 v2(43.9,35.28) ; v2(62.9,31.28) U1.H12 ; U1.AC19 v2(54.9,47.28) ; U1.H18 v2(55.9,31.28) ; v2(59.9,38.28) U1.R15 ; v2(63.9,36.28) U1.N11 ; v2(63.9,26.28) U1.C11 ; U1.L23 v8(50.9,34.28) ; v2(59.9,36.28) U1.N15 ; U1.AA21 v2(52.9,45.28) ; v2(59.9,32.28) U1.J15 ; v2(61.9,47.28) U1.AC13 ; U1.AB20 v2(53.9,46.28) ; v2(63.9,30.28) U1.G11 ; U1.Y18 v2(55.9,44.28) ; U1.B24 v2(49.9,25.28) ; U1.T26 v2(47.9,39.28) ; U1.F26 v2(47.9,29.28) ; U1.J21 v2(52.9,32.28) ; v2(61.9,30.28) U1.G13 ; U1.P18 v2(55.9,37.28) ; U1.V24 v2(49.9,42.28) ; U1.R21 v2(52.9,38.28) ; U1.P24 v2(49.9,37.28) ; v2(60.9,31.28) U1.H14 ; v2(62.9,39.28) U1.T12 ; U1.M20 v2(53.9,35.28) ; U1.E19 v2(54.9,28.28) ; U1.J25 v2(48.9,32.28) ; v2(58.9,39.28) U1.T16 ; U1.A25 v2(48.9,24.28) ; v2(61.9,41.28) U1.U13 ; U1.AA23 v2(50.9,45.28) ; U1.AD24 v2(49.9,48.28) ; U1.M24 v2(49.9,35.28) ; U1.U23 v2(50.9,41.28) ; U1.D26 v2(47.9,27.28) ; U1.J19 v2(54.9,32.28) ; U1.AA17 v2(56.9,45.28) ; U1.D20 v2(53.9,27.28) ; U1.L25 v2(48.9,34.28) ; v2(62.9,42.28) U1.V12 ; v2(60.9,44.28) U1.Y14 ; v2(60.9,39.28) U1.T14 ; v2(58.9,25.28) U1.B16 ; U1.W17 v2(56.9,43.28) ; U1.G21 v2(52.9,30.28) ; U1.H22 v2(51.9,31.28) ; U1.F18 v2(55.9,29.28) ; U1.A19 v2(54.9,24.28) ; v2(63.9,24.28) U1.A11 ; U1.AC17 v2(56.9,47.28) ; U1.A17 v2(56.9,24.28) ; U1.M18 v8(55.9,35.28) ; v2(60.9,27.28) U1.D14 ; U1.K22 v2(51.9,33.28) ; U1.T22 v2(51.9,39.28) ; v2(59.9,34.28) U1.L15 ; U1.K24 v2(49.9,33.28) ; U1.AD26 v2(47.9,48.28) ; v2(61.9,26.28) U1.C13 ; U1.R19 v2(54.9,38.28) ; v2(59.9,49.28) U1.AE15 ; v2(58.9,44.28) U1.Y16 ; U1.U19 v2(54.9,41.28) ; U1.B18 v2(55.9,25.28) ; U1.P26 v2(47.9,37.28) ; U1.G17 v2(56.9,30.28) ; U1.N17 v2(57.9,36.28) ; U1.E27 v2(46.9,28.28) ; v2(61.9,36.28) U1.N13 ; v2(60.9,33.28) U1.K14 ; U1.T20 v2(53.9,39.28) ; v2(62.9,44.28) U1.Y12 ; U1.AD18 v2(55.9,48.28) ; U1.K26 v2(47.9,33.28) ; U1.AE21 v2(52.9,49.28)
  TOP w0.508: C60.1 v5(45.45,18.44)
  BOTTOM w0.254: C200.1 51.4,29.78 v2(50.9,30.28) ; C174.1 53.4,27.78 v2(52.9,28.28) ; v2(47.9,29.28) C167.1 ; v2(61.9,32.28) U1.J13 ; C163.1 59.4,31.78 v2(59.9,32.28) ; C176.1 v2(51.9,27.28) ; v2(63.9,45.28) U1.AA11 ; v2(54.9,32.28) C9.1 ; v2(48.9,41.28) 48.9,40.86 C4.1 ; v2(53.9,46.28) C77.1 ; C11.1 60.24,23.83 60.24,23.94 v2(59.9,24.28) ; v2(61.9,24.28) 61.9,23.52 C12.1 ; C13.1 57.39,28.28 v2(56.9,28.28) ; C173.1 55.4,25.78 v2(54.9,26.28) ; v2(59.9,45.28) U1.AB14 ; C199.1 61.4,29.78 v2(61.9,30.28) ; v2(51.9,39.28) 51.9,39.78 C10.1 ; v2(56.9,26.28) 57.46,26.28 C14.1 ; v2(54.9,45.28) C162.1 ; v2(47.9,48.28) U1.AD26 ; C78.1 v2(60.9,48.28) ; v2(61.9,47.28) U1.AD12 ; v2(47.9,25.28) C79.1 ; v2(62.9,27.28) U1.D12 ; C3.1 57.05,30.14 v2(56.9,30.28) ; C178.1 v2(52.9,47.28) ; v2(63.9,26.28) C80.1 ; v2(63.9,47.28) U1.AC11 ; v2(52.9,32.28) C175.1 ; v2(53.9,29.28) U1.F20 ; v2(56.9,32.28) 57.21,32.59 57.46,32.59 C7.1 ; v2(60.9,27.28) U1.D14 ; v2(56.9,45.28) U1.AA17 57.4,44.38 C5.1 ; v2(63.9,32.28) 63.4,31.78 C177.1
  BOTTOM w0.508: v4(63.74,17.71) 62.24,17.71 v11(61.84,18.12) ; v4(65.01,17.71) 65.01,19.65 v11(65.14,19.77) ; v4(59.17,17.71) 59.17,19.26 v11(58.66,19.77) ; v2(58.9,46.28) 58.61,46 58.28,46 58.07,45.78 L3.1 57.4,45.78 v2(56.9,45.28) ; v2(56.9,49.28) 57.4,49.78 L2.1 58.15,49.78 58.28,49.66 58.28,49.03 58.28,49.02 58.28,48.9 v2(58.9,48.28) ; v11(58.66,14.82) 59.04,14.44 TP37.1 ; C58.1 60.41,19.87 v11(60.31,19.77) 60.44,19.65 v4(60.44,17.71)
  vias: v5(45.45,19.71) v11(60.31,14.82) v11(61.84,19.77) v11(61.84,16.47) v11(61.84,14.82) v11(63.49,19.77) v11(63.49,14.82) v11(65.14,14.82)
